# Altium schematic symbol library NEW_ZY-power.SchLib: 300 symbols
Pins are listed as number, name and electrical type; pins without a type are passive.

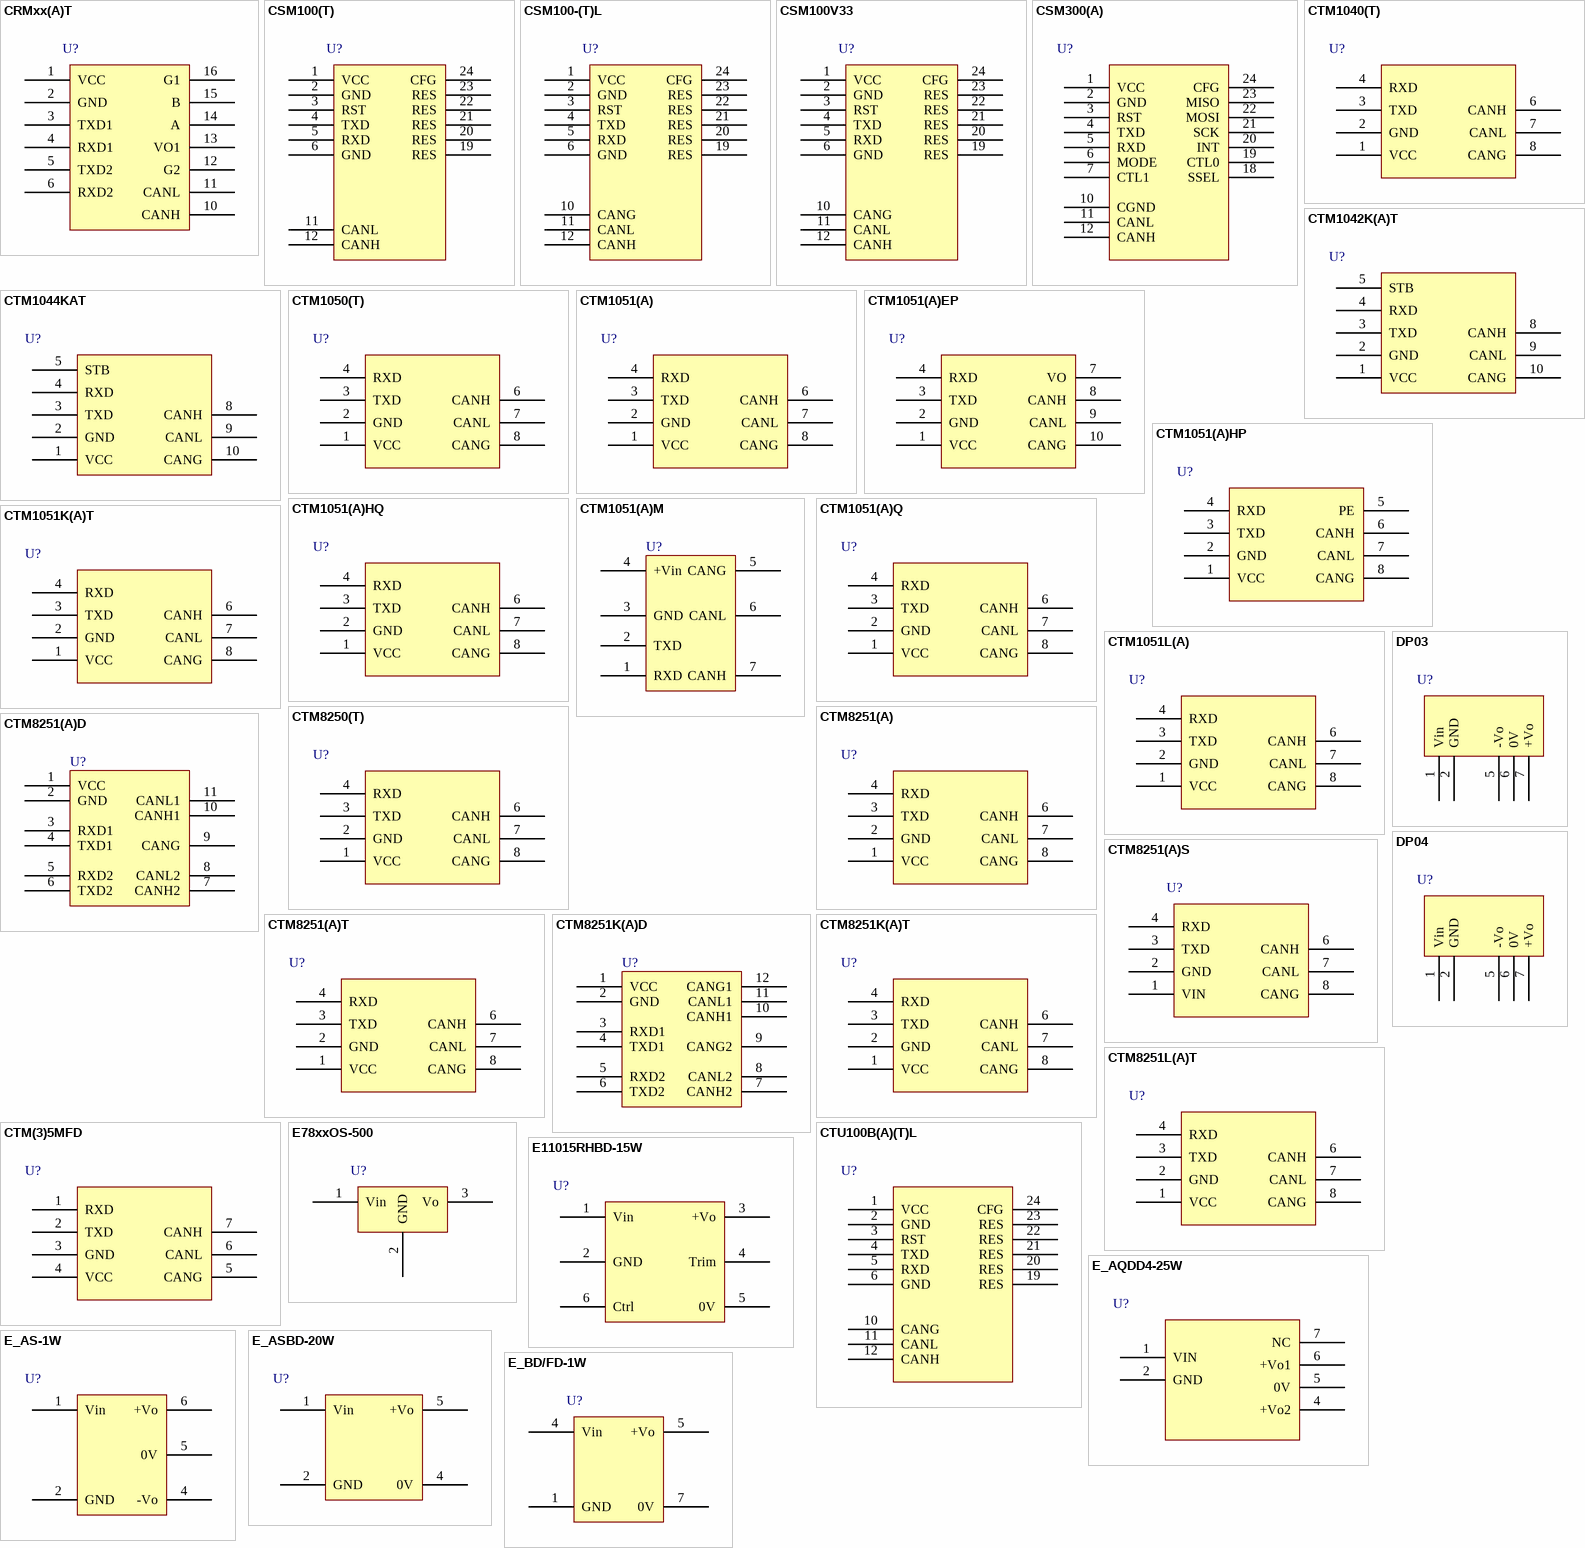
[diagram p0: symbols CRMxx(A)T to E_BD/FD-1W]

## CRMxx(A)T
designator U?
footprint CRMxx(A)T
pins: 1 VCC, 2 GND, 3 TXD1, 4 RXD1, 5 TXD2, 6 RXD2, 10 CANH, 11 CANL, 12 G2, 13 VO1, 14 A, 15 B, 16 G1

## CSM100(T)
designator U?
footprint CSM100(T) (嵌入式CAN-bus接口芯片)
pins: 1 VCC, 2 GND, 3 RST, 4 TXD, 5 RXD, 6 GND, 11 CANL, 12 CANH, 19 RES, 20 RES, 21 RES, 22 RES, 23 RES, 24 CFG

## CSM100-(T)L
designator U?
footprint CSM100-(T)L
pins: 1 VCC, 2 GND, 3 RST, 4 TXD, 5 RXD, 6 GND, 10 CANG, 11 CANL, 12 CANH, 19 RES, 20 RES, 21 RES, 22 RES, 23 RES, 24 CFG

## CSM100V33
designator U?
footprint CSM100V33
pins: 1 VCC, 2 GND, 3 RST, 4 TXD, 5 RXD, 6 GND, 10 CANG, 11 CANL, 12 CANH, 19 RES, 20 RES, 21 RES, 22 RES, 23 RES, 24 CFG

## CSM300(A)
designator U?
footprint CSM300(A)
pins: 1 VCC, 2 GND, 3 RST, 4 TXD, 5 RXD, 6 MODE, 7 CTL1, 10 CGND, 11 CANL, 12 CANH, 18 SSEL, 19 CTL0, 20 INT, 21 SCK, 22 MOSI, 23 MISO, 24 CFG

## CTM1040(T)
designator U?
footprint CTM1040(T)
pins: 1 VCC, 2 GND, 3 TXD, 4 RXD, 6 CANH, 7 CANL, 8 CANG

## CTM1042K(A)T
designator U?
footprint CTM1042K(A)T
pins: 1 VCC, 2 GND, 3 TXD, 4 RXD, 5 STB, 8 CANH, 9 CANL, 10 CANG

## CTM1044KAT
designator U?
footprint CTM1044KAT
pins: 1 VCC, 2 GND, 3 TXD, 4 RXD, 5 STB, 8 CANH, 9 CANL, 10 CANG

## CTM1050(T)
designator U?
footprint CTM1050(T)
pins: 1 VCC, 2 GND, 3 TXD, 4 RXD, 6 CANH, 7 CANL, 8 CANG

## CTM1051(A)
designator U?
footprint CTM1051(A)
pins: 1 VCC, 2 GND, 3 TXD, 4 RXD, 6 CANH, 7 CANL, 8 CANG

## CTM1051(A)EP
designator U?
footprint CTM1051(A)EP (Footprint not found)
pins: 1 VCC, 2 GND, 3 TXD, 4 RXD, 7 VO, 8 CANH, 9 CANL, 10 CANG

## CTM1051(A)HP
designator U?
footprint CTM1051(A)HP
pins: 1 VCC, 2 GND, 3 TXD, 4 RXD, 5 PE, 6 CANH, 7 CANL, 8 CANG

## CTM1051(A)HQ
designator U?
footprint CTM1051(A)HQ
pins: 1 VCC, 2 GND, 3 TXD, 4 RXD, 6 CANH, 7 CANL, 8 CANG

## CTM1051(A)M
designator U?
footprint CTM1051(A)M
pins: 1 RXD, 2 TXD, 3 GND, 4 +Vin, 5 CANG, 6 CANL, 7 CANH

## CTM1051(A)Q
designator U?
footprint CTM1051(A)Q
pins: 1 VCC, 2 GND, 3 TXD, 4 RXD, 6 CANH, 7 CANL, 8 CANG

## CTM1051K(A)T
designator U?
footprint CTM1051K(A)T
pins: 1 VCC, 2 GND, 3 TXD, 4 RXD, 6 CANH, 7 CANL, 8 CANG

## CTM1051L(A)
designator U?
footprint CTM1051L(A)
pins: 1 VCC, 2 GND, 3 TXD, 4 RXD, 6 CANH, 7 CANL, 8 CANG

## CTM8250(T)
designator U?
footprint CTM8250(T)
pins: 1 VCC, 2 GND, 3 TXD, 4 RXD, 6 CANH, 7 CANL, 8 CANG

## CTM8251(A)
designator U?
footprint CTM8251(A)
pins: 1 VCC, 2 GND, 3 TXD, 4 RXD, 6 CANH, 7 CANL, 8 CANG

## CTM8251(A)D
designator U?
footprint CTM8251(A)D
pins: 1 VCC, 2 GND, 3 RXD1, 4 TXD1, 5 RXD2, 6 TXD2, 7 CANH2, 8 CANL2, 9 CANG, 10 CANH1, 11 CANL1

## CTM8251(A)S
designator U?
footprint CTM8251(A)S
pins: 1 VIN, 2 GND, 3 TXD, 4 RXD, 6 CANH, 7 CANL, 8 CANG

## CTM8251(A)T
designator U?
footprint CTM8251(A)T
pins: 1 VCC, 2 GND, 3 TXD, 4 RXD, 6 CANH, 7 CANL, 8 CANG

## CTM8251K(A)D
designator U?
footprint CTM8251K(A)D
pins: 1 VCC, 2 GND, 3 RXD1, 4 TXD1, 5 RXD2, 6 TXD2, 7 CANH2, 8 CANL2, 9 CANG2, 10 CANH1, 11 CANL1, 12 CANG1

## CTM8251K(A)T
designator U?
footprint CTM8251K(A)T
pins: 1 VCC, 2 GND, 3 TXD, 4 RXD, 6 CANH, 7 CANL, 8 CANG

## CTM8251L(A)T
designator U?
footprint CTM8251L(A)T
pins: 1 VCC, 2 GND, 3 TXD, 4 RXD, 6 CANH, 7 CANL, 8 CANG

## CTM(3)5MFD
designator U?
footprint CTM(3)5MFD
pins: 1 RXD, 2 TXD, 3 GND, 4 VCC, 5 CANG, 6 CANL, 7 CANH

## CTU100B(A)(T)L
designator U?
footprint CTU100B(A)(T)L
pins: 1 VCC, 2 GND, 3 RST, 4 TXD, 5 RXD, 6 GND, 10 CANG, 11 CANL, 12 CANH, 19 RES, 20 RES, 21 RES, 22 RES, 23 RES, 24 CFG

## DP03
designator U?
footprint DP03
pins: 1 Vin, 2 GND, 5 -Vo, 6 0V, 7 +Vo

## DP04
designator U?
footprint DP04
pins: 1 Vin, 2 GND, 5 -Vo, 6 0V, 7 +Vo

## E78xxOS-500
designator U?
footprint E78xxOS-500
pins: 1 Vin, 2 GND, 3 Vo

## E11015RHBD-15W
designator U?
footprint E11015RHBD-15W
pins: 1 Vin, 2 GND, 3 +Vo, 4 Trim, 5 0V, 6 Ctrl

## E_AQDD4-25W
designator U?
footprint E_AQDD4-25W
pins: 1 VIN, 2 GND, 4 +Vo2, 5 0V, 6 +Vo1, 7 NC

## E_AS-1W
designator U?
footprint E_AS-1W
pins: 1 Vin, 2 GND, 4 -Vo, 5 0V, 6 +Vo

## E_ASBD-20W
designator U?
footprint E_ASBD-20W
pins: 1 Vin, 2 GND, 4 0V, 5 +Vo

## E_BD/FD-1W
designator U?
footprint E_BD/FD-1W
pins: 1 GND, 4 Vin, 5 +Vo, 7 0V

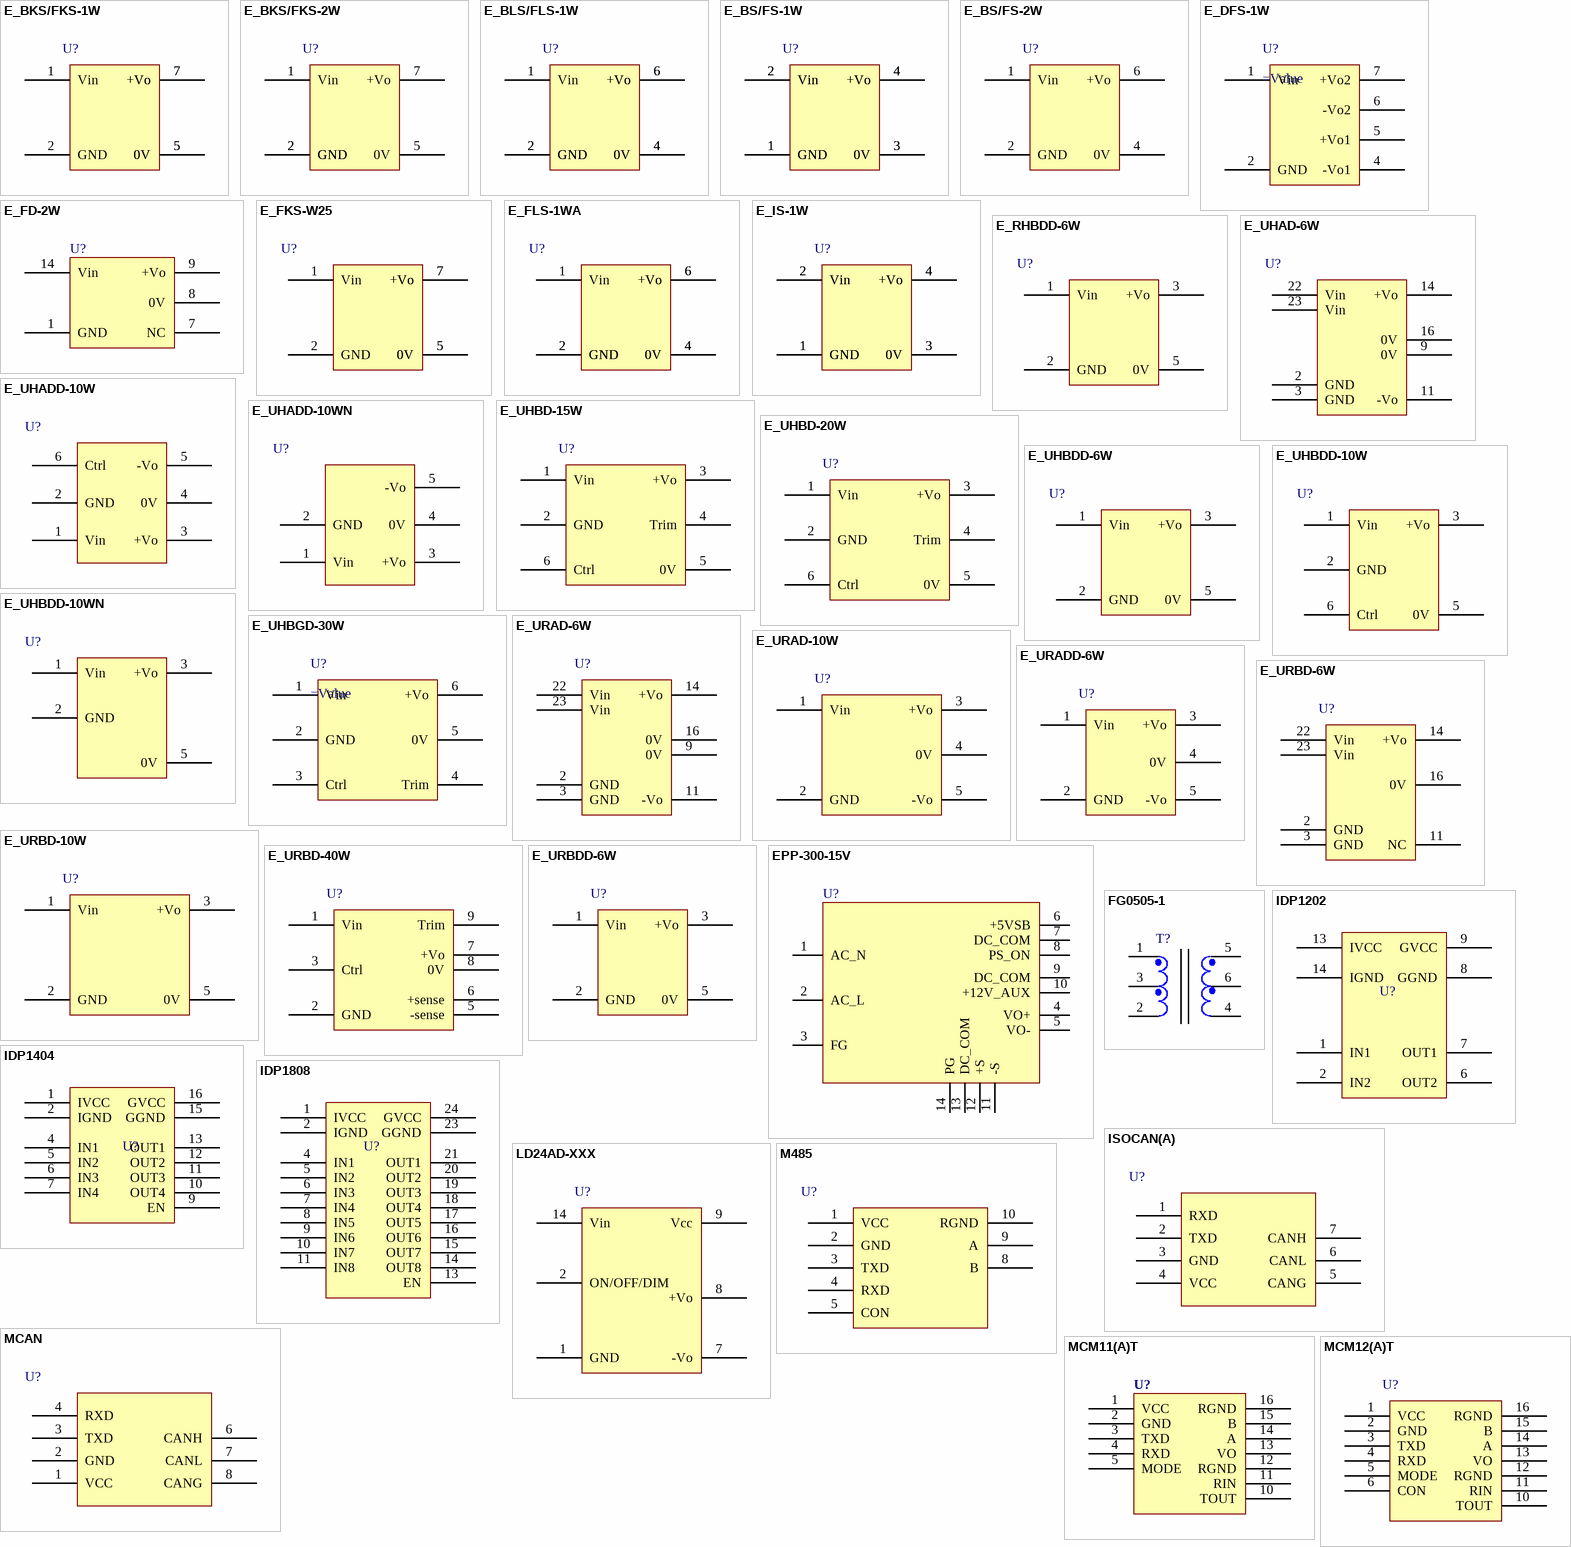
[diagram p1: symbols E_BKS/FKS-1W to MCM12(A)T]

## E_BKS/FKS-1W
designator U?
footprint E_BKS/FKS-1W
pins: 1 Vin, 2 GND, 5 0V, 5 0V, 7 +Vo, 7 +Vo

## E_BKS/FKS-2W
designator U?
footprint E_BKS/FKS-2W
pins: 1 Vin, 2 GND, 2 GND, 5 0V, 7 +Vo

## E_BLS/FLS-1W
designator U?
footprint E_BLS/FLS-1W
pins: 1 Vin, 2 GND, 2 GND, 4 0V, 4 0V, 6 +Vo, 6 +Vo

## E_BS/FS-1W
designator U?
footprint E_BS/FS-1W
pins: 1 GND, 1 GND, 2 Vin, 2 Vin, 3 0V, 3 0V, 4 +Vo, 4 +Vo

## E_BS/FS-2W
designator U?
footprint E_BS/FS-2W
pins: 1 Vin, 2 GND, 4 0V, 6 +Vo

## E_DFS-1W
designator U?
footprint E_DFS-1W
pins: 1 Vin, 2 GND, 4 -Vo1, 5 +Vo1, 6 -Vo2, 7 +Vo2

## E_FD-2W
designator U?
footprint E_FD-2W
pins: 1 GND, 7 NC, 8 0V, 9 +Vo, 14 Vin

## E_FKS-W25
designator U?
footprint E_FKS-W25
pins: 1 Vin, 2 GND, 5 0V, 5 0V, 7 +Vo, 7 +Vo

## E_FLS-1WA
designator U?
footprint E_FLS-1WA
pins: 1 Vin, 2 GND, 2 GND, 4 0V, 4 0V, 6 +Vo, 6 +Vo

## E_IS-1W
designator U?
footprint E_IS-1W
pins: 1 GND, 1 GND, 2 Vin, 2 Vin, 3 0V, 3 0V, 4 +Vo, 4 +Vo

## E_RHBDD-6W
designator U?
footprint E_RHBDD-6W
pins: 1 Vin, 2 GND, 3 +Vo, 5 0V

## E_UHAD-6W
designator U?
footprint E_UHAD-6W
pins: 2 GND, 3 GND, 9 0V, 11 -Vo, 14 +Vo, 16 0V, 22 Vin, 23 Vin

## E_UHADD-10W
designator U?
footprint E_UHADD-10W
pins: 1 Vin, 2 GND, 3 +Vo, 4 0V, 5 -Vo, 6 Ctrl

## E_UHADD-10WN
designator U?
footprint E_UHADD-10WN
pins: 1 Vin, 2 GND, 3 +Vo, 4 0V, 5 -Vo

## E_UHBD-15W
designator U?
footprint E_UHBD-15W
pins: 1 Vin, 2 GND, 3 +Vo, 4 Trim, 5 0V, 6 Ctrl

## E_UHBD-20W
designator U?
footprint E_UHBD-20W
pins: 1 Vin, 2 GND, 3 +Vo, 4 Trim, 5 0V, 6 Ctrl

## E_UHBDD-6W
designator U?
footprint E_UHBDD-6W
pins: 1 Vin, 2 GND, 3 +Vo, 5 0V

## E_UHBDD-10W
designator U?
footprint E_UHBDD-10W
pins: 1 Vin, 2 GND, 3 +Vo, 5 0V, 6 Ctrl

## E_UHBDD-10WN
designator U?
footprint E_UHBDD-10WN
pins: 1 Vin, 2 GND, 3 +Vo, 5 0V

## E_UHBGD-30W
designator U?
footprint E_UHBGD-30W
pins: 1 Vin, 2 GND, 3 Ctrl, 4 Trim, 5 0V, 6 +Vo

## E_URAD-6W
designator U?
footprint E_URAD-6W
pins: 2 GND, 3 GND, 9 0V, 11 -Vo, 14 +Vo, 16 0V, 22 Vin, 23 Vin

## E_URAD-10W
designator U?
footprint E_URAD-10W
pins: 1 Vin, 2 GND, 3 +Vo, 4 0V, 5 -Vo

## E_URADD-6W
designator U?
footprint E_URADD-6W
pins: 1 Vin, 2 GND, 3 +Vo, 4 0V, 5 -Vo

## E_URBD-6W
designator U?
footprint E_URBD-6W
pins: 2 GND, 3 GND, 11 NC, 14 +Vo, 16 0V, 22 Vin, 23 Vin

## E_URBD-10W
designator U?
footprint E_URBD-10W
pins: 1 Vin, 2 GND, 3 +Vo, 5 0V

## E_URBD-40W
designator U?
footprint E_URBD-40W
pins: 1 Vin, 2 GND, 3 Ctrl, 5 -sense, 6 +sense, 7 +Vo, 8 0V, 9 Trim

## E_URBDD-6W
designator U?
footprint E_URBDD-6W
pins: 1 Vin, 2 GND, 3 +Vo, 5 0V

## EPP-300-15V
designator U?
footprint epp-300-15V
pins: 1 AC_N, 2 AC_L, 3 FG, 4 VO+, 5 VO-, 6 +5VSB, 7 DC_COM, 8 PS_ON, 9 DC_COM, 10 +12V_AUX, 11 -S, 12 +S, 13 DC_COM, 14 PG

## FG0505-1
designator T?
TRANS6D
footprint FG0505-1
pins: 1, 2, 3, 4, 5, 6

## IDP1202
designator U?
footprint IDP1202 (20x10x8mm)
pins: 1 IN1, 2 IN2, 6 OUT2, 7 OUT1, 8 GGND, 9 GVCC, 13 IVCC, 14 IGND

## IDP1404
designator U?
footprint IDP1404 (23.97x14.41x9.65mm)
pins: 1 IVCC, 2 IGND, 4 IN1, 5 IN2, 6 IN3, 7 IN4, 9 EN, 10 OUT4, 11 OUT3, 12 OUT2, 13 OUT1, 15 GGND, 16 GVCC

## IDP1808
designator U?
footprint IDP1808 (32.32x14.41x6.7(9.65)mm)
pins: 1 IVCC, 2 IGND, 4 IN1, 5 IN2, 6 IN3, 7 IN4, 8 IN5, 9 IN6, 10 IN7, 11 IN8, 13 EN, 14 OUT8, 15 OUT7, 16 OUT6, 17 OUT5, 18 OUT4, 19 OUT3, 20 OUT2, 21 OUT1, 23 GGND, 24 GVCC

## ISOCAN(A)
designator U?
footprint ISOCAN(A)
pins: 1 RXD, 2 TXD, 3 GND, 4 VCC, 5 CANG, 6 CANL, 7 CANH

## LD24AD-XXX
designator U?
footprint LD24AD-XXX
pins: 1 GND, 2 ON/OFF/DIM, 7 -Vo, 8 +Vo, 9 Vcc, 14 Vin

## M485
designator U?
footprint M485
pins: 1 VCC, 2 GND, 3 TXD, 4 RXD, 5 CON, 8 B, 9 A, 10 RGND

## MCAN
designator U?
footprint MCAN
pins: 1 VCC, 2 GND, 3 TXD, 4 RXD, 6 CANH, 7 CANL, 8 CANG

## MCM11(A)T
designator U?
footprint MCM11(A)T
pins: 1 VCC, 2 GND, 3 TXD, 4 RXD, 5 MODE, 10 TOUT, 11 RIN, 12 RGND, 13 VO, 14 A, 15 B, 16 RGND

## MCM12(A)T
designator U?
footprint MCM12(A)T
pins: 1 VCC, 2 GND, 3 TXD, 4 RXD, 5 MODE, 6 CON, 10 TOUT, 11 RIN, 12 RGND, 13 VO, 14 A, 15 B, 16 RGND

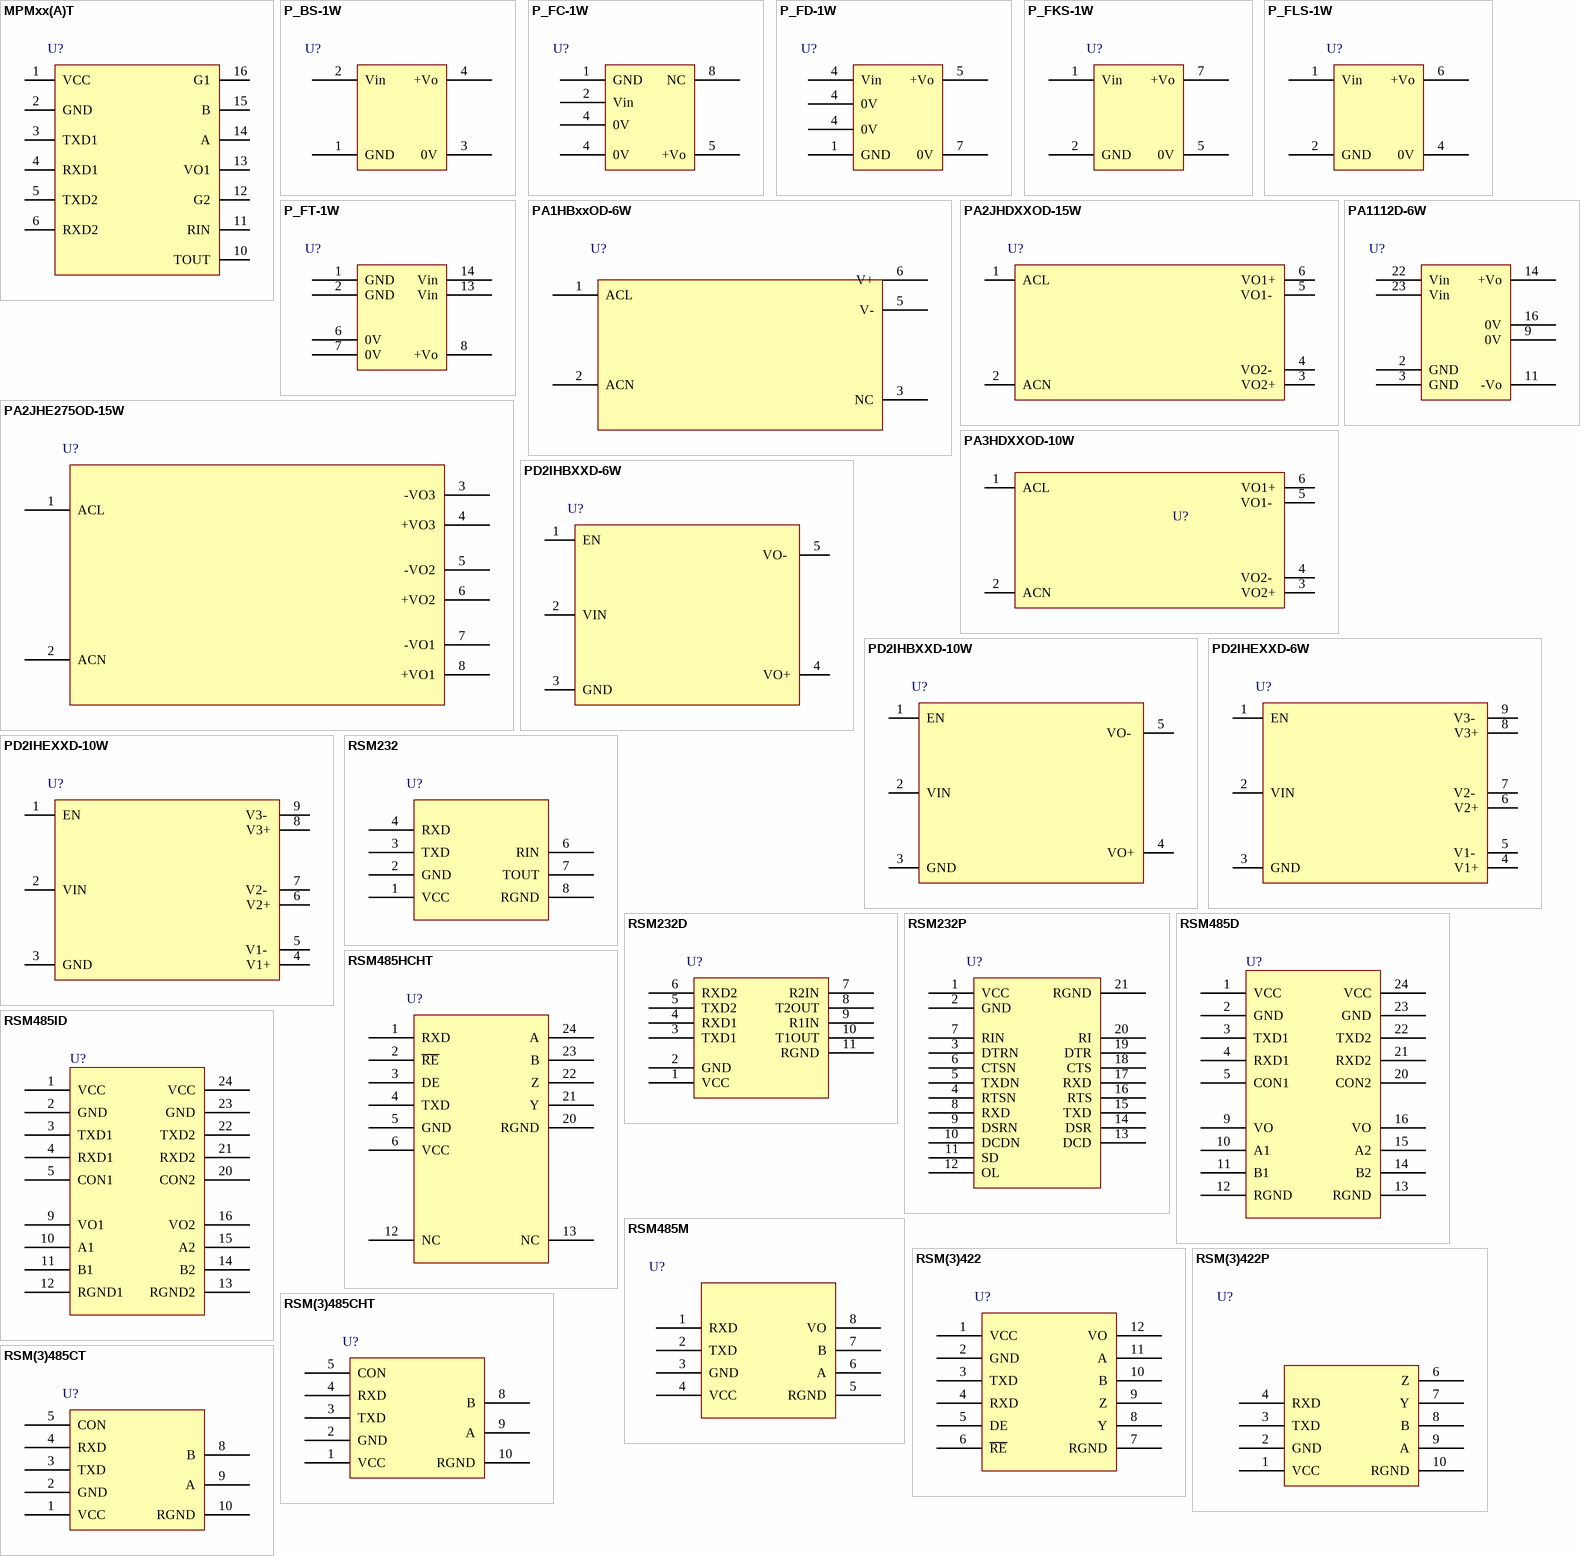
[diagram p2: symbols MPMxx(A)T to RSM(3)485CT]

## MPMxx(A)T
designator U?
footprint MPMxx(A)T
pins: 1 VCC, 2 GND, 3 TXD1, 4 RXD1, 5 TXD2, 6 RXD2, 10 TOUT, 11 RIN, 12 G2, 13 VO1, 14 A, 15 B, 16 G1

## P_BS-1W
designator U?
footprint Model Name (Footprint not found)
footprint P_BS-1W
pins: 1 GND, 2 Vin, 3 0V, 4 +Vo

## P_FC-1W
designator U?
footprint P_FC-1W
pins: 1 GND, 2 Vin, 4 0V, 4 0V, 5 +Vo, 8 NC

## P_FD-1W
designator U?
footprint P_FD-1W
pins: 1 GND, 4 Vin, 4 0V, 4 0V, 5 +Vo, 7 0V

## P_FKS-1W
designator U?
footprint P_FKS-1W
pins: 1 Vin, 2 GND, 5 0V, 7 +Vo

## P_FLS-1W
designator U?
footprint P_FLS-1W
pins: 1 Vin, 2 GND, 4 0V, 6 +Vo

## P_FT-1W
designator U?
footprint P_FT-1W
pins: 1 GND, 2 GND, 6 0V, 7 0V, 8 +Vo, 13 Vin, 14 Vin

## PA1HBxxOD-6W
designator U?
footprint PA1HBxxOD-6W
pins: 1 ACL, 2 ACN, 3 NC, 5 V-, 6 V+

## PA2JHDXXOD-15W
designator U?
footprint PA2JHDXXOD-15W
pins: 1 ACL, 2 ACN, 3 VO2+, 4 VO2- , 5 VO1- , 6 VO1+

## PA2JHE275OD-15W
designator U?
footprint PA2JHE275OD-15W
pins: 1 ACL, 2 ACN, 3 -VO3, 4 +VO3, 5 -VO2, 6 +VO2, 7 -VO1, 8 +VO1

## PA3HDXXOD-10W
designator U?
footprint PA3HDXXOD-10W
pins: 1 ACL, 2 ACN, 3 VO2+, 4 VO2- , 5 VO1- , 6 VO1+

## PA1112D-6W
designator U?
footprint PA1112D-6W
pins: 2 GND, 3 GND, 9 0V, 11 -Vo, 14 +Vo, 16 0V, 22 Vin, 23 Vin

## PD2IHBXXD-6W
designator U?
footprint PD2IHBXXD-6W
pins: 1 EN, 2 VIN, 3 GND, 4 VO+, 5 VO- 

## PD2IHBXXD-10W
designator U?
footprint PD2IHBXXD-10W
pins: 1 EN, 2 VIN, 3 GND, 4 VO+, 5 VO- 

## PD2IHEXXD-6W
designator U?
footprint PD2IHEXXD-6W
pins: 1 EN, 2 VIN, 3 GND, 4 V1+, 5 V1- , 6 V2+, 7 V2- , 8 V3+, 9 V3- 

## PD2IHEXXD-10W
designator U?
footprint PD2IHEXXD-10W
pins: 1 EN, 2 VIN, 3 GND, 4 V1+, 5 V1- , 6 V2+, 7 V2- , 8 V3+, 9 V3- 

## RSM232
designator U?
footprint RSM232
pins: 1 VCC, 2 GND, 3 TXD, 4 RXD, 6 RIN, 7 TOUT, 8 RGND

## RSM232D
designator U?
footprint RSM232D
pins: 1 VCC, 2 GND, 3 TXD1, 4 RXD1, 5 TXD2, 6 RXD2, 7 R2IN, 8 T2OUT, 9 R1IN, 10 T1OUT, 11 RGND

## RSM232P
designator U?
footprint RSM232P
pins: 1 VCC, 2 GND, 3 DTRN, 4 RTSN, 5 TXDN, 6 CTSN, 7 RIN, 8 RXD, 9 DSRN, 10 DCDN, 11 SD, 12 OL, 13 DCD, 14 DSR, 15 TXD, 16 RTS, 17 RXD, 18 CTS, 19 DTR, 20 RI, 21 RGND

## RSM485D
designator U?
footprint RSM485D
pins: 1 VCC, 2 GND, 3 TXD1, 4 RXD1, 5 CON1, 9 VO, 10 A1, 11 B1, 12 RGND, 13 RGND, 14 B2, 15 A2, 16 VO, 20 CON2, 21 RXD2, 22 TXD2, 23 GND, 24 VCC
2 alternate drawings of the same symbol

## RSM485HCHT
designator U?
footprint RSM485HCHT
pins: 1 RXD, 2 ~{RE}, 3 DE, 4 TXD, 5 GND, 6 VCC, 12 NC, 13 NC, 20 RGND, 21 Y, 22 Z, 23 B, 24 A

## RSM485ID
designator U?
footprint RSM485ID
pins: 1 VCC, 2 GND, 3 TXD1, 4 RXD1, 5 CON1, 9 VO1, 10 A1, 11 B1, 12 RGND1, 13 RGND2, 14 B2, 15 A2, 16 VO2, 20 CON2, 21 RXD2, 22 TXD2, 23 GND, 24 VCC
2 alternate drawings of the same symbol

## RSM485M
designator U?
footprint RSM485M
pins: 1 RXD, 2 TXD, 3 GND, 4 VCC, 5 RGND, 6 A, 7 B, 8 VO

## RSM(3)422
designator U?
footprint RSM(3)422
pins: 1 VCC, 2 GND, 3 TXD, 4 RXD, 5 DE, 6 ~{RE}, 7 RGND, 8 Y, 9 Z, 10 B, 11 A, 12 VO

## RSM(3)422P
designator U?
footprint RSM(3)422P
pins: 1 VCC, 2 GND, 3 TXD, 4 RXD, 6 Z, 7 Y, 8 B, 9 A, 10 RGND
2 alternate drawings of the same symbol

## RSM(3)485CHT
designator U?
footprint RSM(3)485CHT (嵌入式隔离RS-485收发器)
pins: 1 VCC, 2 GND, 3 TXD, 4 RXD, 5 CON, 8 B, 9 A, 10 RGND

## RSM(3)485CT
designator U?
footprint RSM(3)485CT (嵌入式隔离RS-485收发器)
pins: 1 VCC, 2 GND, 3 TXD, 4 RXD, 5 CON, 8 B, 9 A, 10 RGND

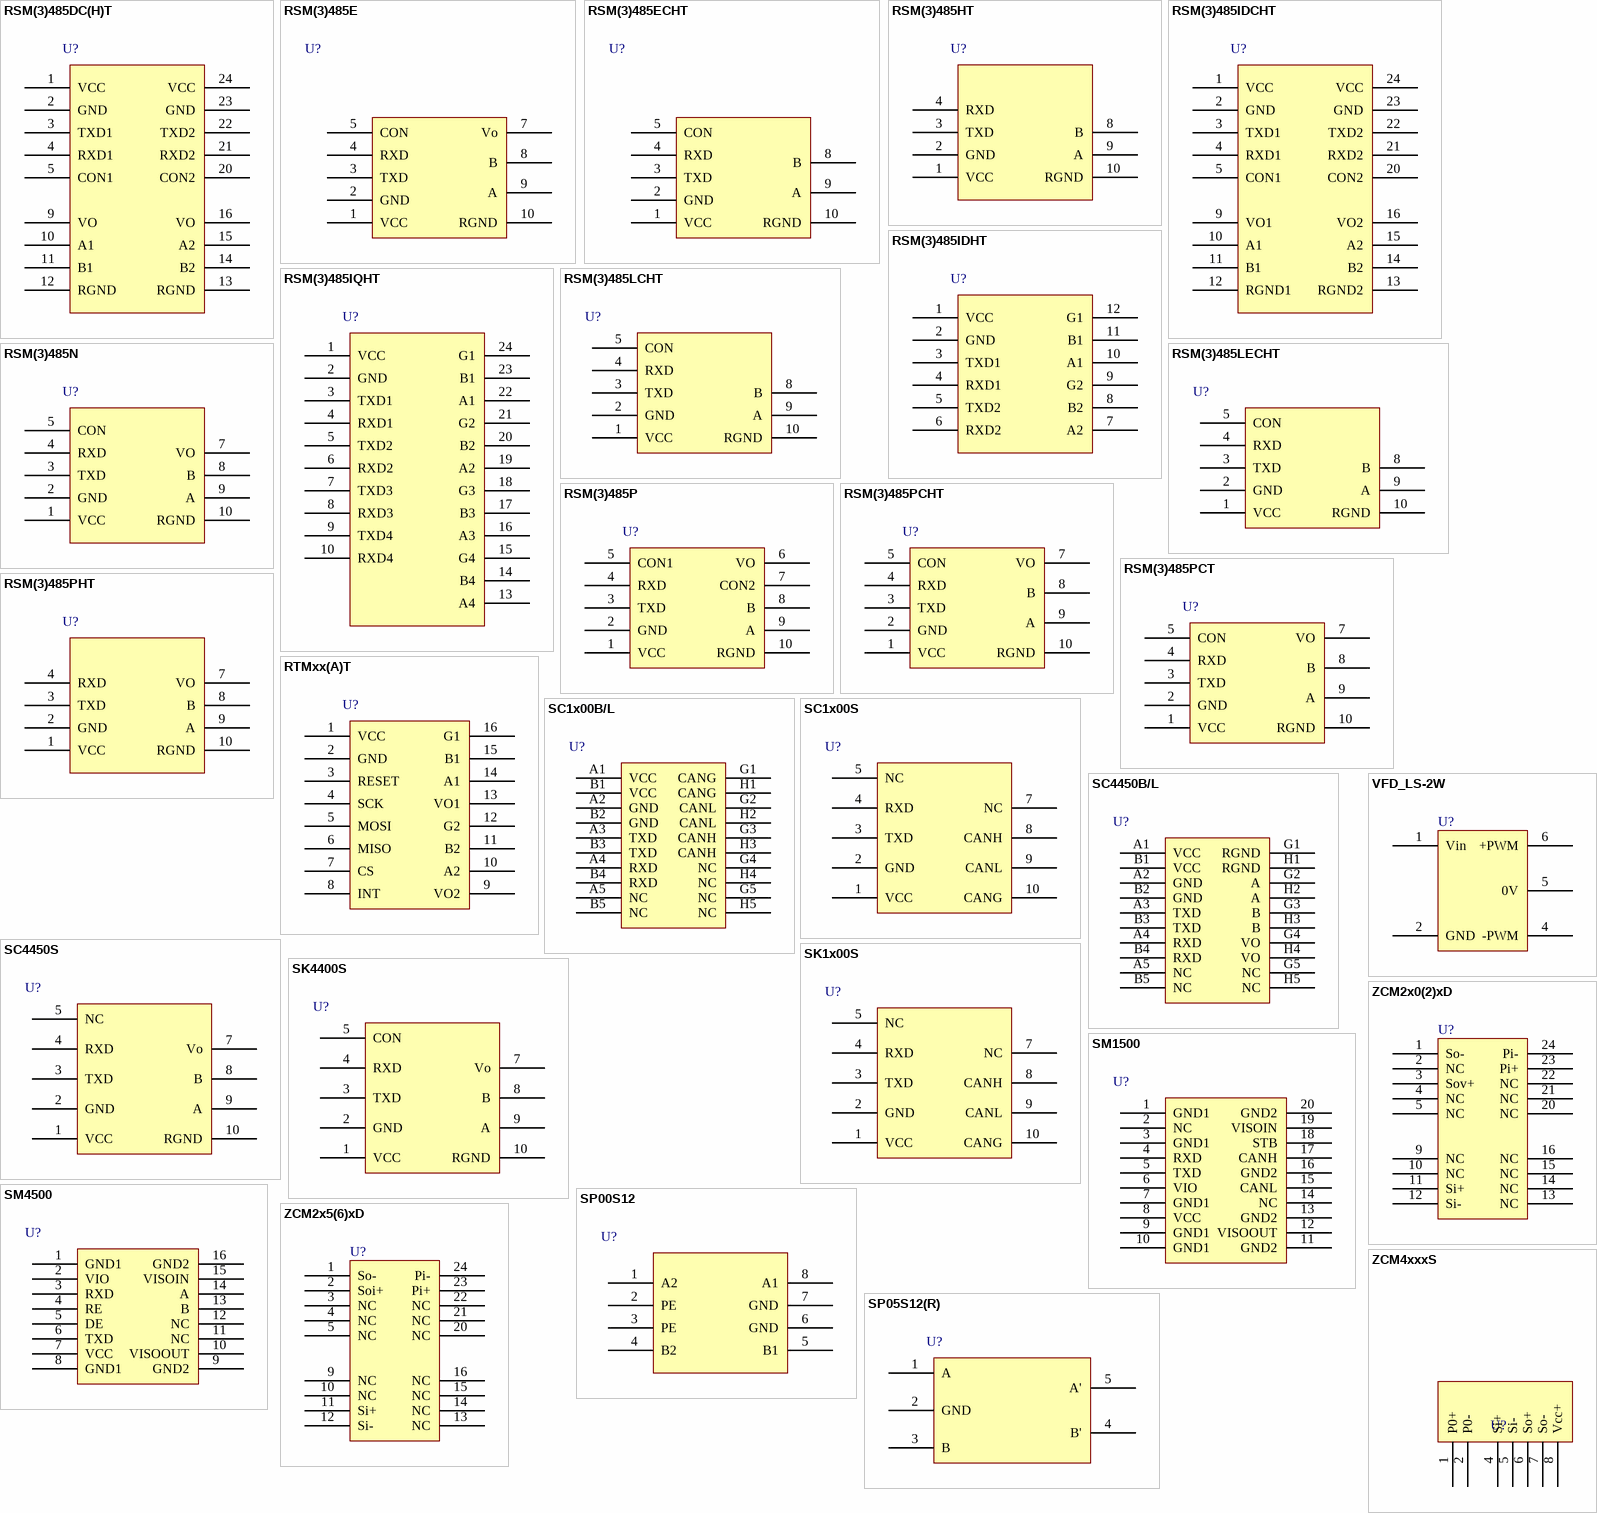
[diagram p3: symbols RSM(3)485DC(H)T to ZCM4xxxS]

## RSM(3)485DC(H)T
designator U?
footprint RSM(3)485DC(H)T
pins: 1 VCC, 2 GND, 3 TXD1, 4 RXD1, 5 CON1, 9 VO, 10 A1, 11 B1, 12 RGND, 13 RGND, 14 B2, 15 A2, 16 VO, 20 CON2, 21 RXD2, 22 TXD2, 23 GND, 24 VCC

## RSM(3)485E
designator U?
footprint RSM(3)485E
pins: 1 VCC, 2 GND, 3 TXD, 4 RXD, 5 CON, 7 Vo, 8 B, 9 A, 10 RGND
2 alternate drawings of the same symbol

## RSM(3)485ECHT
designator U?
footprint RSM(3)485ECHT
pins: 1 VCC, 2 GND, 3 TXD, 4 RXD, 5 CON, 8 B, 9 A, 10 RGND
2 alternate drawings of the same symbol

## RSM(3)485HT
designator U?
footprint RSM(3)485HT
pins: 1 VCC, 2 GND, 3 TXD, 4 RXD, 8 B, 9 A, 10 RGND

## RSM(3)485IDCHT
designator U?
footprint RSM(3)485IDCHT
pins: 1 VCC, 2 GND, 3 TXD1, 4 RXD1, 5 CON1, 9 VO1, 10 A1, 11 B1, 12 RGND1, 13 RGND2, 14 B2, 15 A2, 16 VO2, 20 CON2, 21 RXD2, 22 TXD2, 23 GND, 24 VCC

## RSM(3)485IDHT
designator U?
footprint RSM(3)485IDHT
pins: 1 VCC, 2 GND, 3 TXD1, 4 RXD1, 5 TXD2, 6 RXD2, 7 A2, 8 B2, 9 G2, 10 A1, 11 B1, 12 G1

## RSM(3)485IQHT
designator U?
footprint RSM(3)485IQHT
pins: 1 VCC, 2 GND, 3 TXD1, 4 RXD1, 5 TXD2, 6 RXD2, 7 TXD3, 8 RXD3, 9 TXD4, 10 RXD4, 13 A4, 14 B4, 15 G4, 16 A3, 17 B3, 18 G3, 19 A2, 20 B2, 21 G2, 22 A1, 23 B1, 24 G1

## RSM(3)485LCHT
designator U?
footprint RSM(3)485LCHT
pins: 1 VCC, 2 GND, 3 TXD, 4 RXD, 5 CON, 8 B, 9 A, 10 RGND

## RSM(3)485LECHT
designator U?
footprint RSM(3)485LECHT
pins: 1 VCC, 2 GND, 3 TXD, 4 RXD, 5 CON, 8 B, 9 A, 10 RGND

## RSM(3)485N
designator U?
footprint RSM(3)485N
pins: 1 VCC, 2 GND, 3 TXD, 4 RXD, 5 CON, 7 VO, 8 B, 9 A, 10 RGND

## RSM(3)485P
designator U?
footprint RSM(3)485P
pins: 1 VCC, 2 GND, 3 TXD, 4 RXD, 5 CON1, 6 VO, 7 CON2, 8 B, 9 A, 10 RGND

## RSM(3)485PCHT
designator U?
footprint RSM(3)485PCHT
pins: 1 VCC, 2 GND, 3 TXD, 4 RXD, 5 CON, 7 VO, 8 B, 9 A, 10 RGND

## RSM(3)485PCT
designator U?
footprint RSM(3)485PCT
pins: 1 VCC, 2 GND, 3 TXD, 4 RXD, 5 CON, 7 VO, 8 B, 9 A, 10 RGND

## RSM(3)485PHT
designator U?
footprint RSM(3)485PHT
pins: 1 VCC, 2 GND, 3 TXD, 4 RXD, 7 VO, 8 B, 9 A, 10 RGND

## RTMxx(A)T
designator U?
footprint RTMxx(A)T
pins: 1 VCC, 2 GND, 3 RESET, 4 SCK, 5 MOSI, 6 MISO, 7 CS, 8 INT, 9 VO2, 10 A2, 11 B2, 12 G2, 13 VO1, 14 A1, 15 B1, 16 G1

## SC1x00B/L
designator U?
footprint SC1x00B/L
pins: A1 VCC, A2 GND, A3 TXD, A4 RXD, A5 NC, B1 VCC, B2 GND, B3 TXD, B4 RXD, B5 NC, G1 CANG, G2 CANL, G3 CANH, G4 NC, G5 NC, H1 CANG, H2 CANL, H3 CANH, H4 NC, H5 NC

## SC1x00S
designator U?
footprint SC1x00S
pins: 1 VCC, 2 GND, 3 TXD, 4 RXD, 5 NC, 7 NC, 8 CANH, 9 CANL, 10 CANG

## SC4450B/L
designator U?
footprint SC4450B/L
pins: A1 VCC, A2 GND, A3 TXD, A4 RXD, A5 NC, B1 VCC, B2 GND, B3 TXD, B4 RXD, B5 NC, G1 RGND, G2 A, G3 B, G4 VO, G5 NC, H1 RGND, H2 A, H3 B, H4 VO, H5 NC

## SC4450S
designator U?
footprint SC4450S
pins: 1 VCC, 2 GND, 3 TXD, 4 RXD, 5 NC, 7 Vo, 8 B, 9 A, 10 RGND

## SK1x00S
designator U?
footprint SK1x00S
pins: 1 VCC, 2 GND, 3 TXD, 4 RXD, 5 NC, 7 NC, 8 CANH, 9 CANL, 10 CANG

## SK4400S
designator U?
footprint SK4400S
pins: 1 VCC, 2 GND, 3 TXD, 4 RXD, 5 CON, 7 Vo, 8 B, 9 A, 10 RGND

## SM1500
designator U?
footprint SM1500
pins: 1 GND1, 2 NC, 3 GND1, 4 RXD, 5 TXD, 6 VIO, 7 GND1, 8 VCC, 9 GND1, 10 GND1, 11 GND2, 12 VISOOUT, 13 GND2, 14 NC, 15 CANL, 16 GND2, 17 CANH, 18 STB, 19 VISOIN, 20 GND2

## SM4500
designator U?
footprint SM4500
pins: 1 GND1, 2 VIO, 3 RXD, 4 RE, 5 DE, 6 TXD, 7 VCC, 8 GND1, 9 GND2, 10 VISOOUT, 11 NC, 12 NC, 13 B, 14 A, 15 VISOIN, 16 GND2

## SP00S12
designator U?
footprint SP00S12
pins: 1 A2, 2 PE, 3 PE, 4 B2, 5 B1, 6 GND, 7 GND, 8 A1

## SP05S12(R)
designator U?
footprint SP05S12(R)
pins: 1 A, 2 GND, 3 B, 4 B', 5 A'

## VFD_LS-2W
designator U?
footprint VFD_LS-2W
pins: 1 Vin, 2 GND, 4 -PWM, 5 0V, 6 +PWM

## ZCM2x0(2)xD
designator U?
footprint ZCM2x0(2)xD
pins: 1 So-, 2 NC, 3 Sov+, 4 NC, 5 NC, 9 NC, 10 NC, 11 Si+, 12 Si-, 13 NC, 14 NC, 15 NC, 16 NC, 20 NC, 21 NC, 22 NC, 23 Pi+, 24 Pi-

## ZCM2x5(6)xD
designator U?
footprint ZCM2x5(6)xD
pins: 1 So-, 2 Soi+, 3 NC, 4 NC, 5 NC, 9 NC, 10 NC, 11 Si+, 12 Si-, 13 NC, 14 NC, 15 NC, 16 NC, 20 NC, 21 NC, 22 NC, 23 Pi+, 24 Pi-

## ZCM4xxxS
designator U?
footprint ZCM4XXXS
pins: 1 P0+, 2 P0-, 4 Si+, 5 Si-, 6 So+, 7 So-, 8 Vcc+

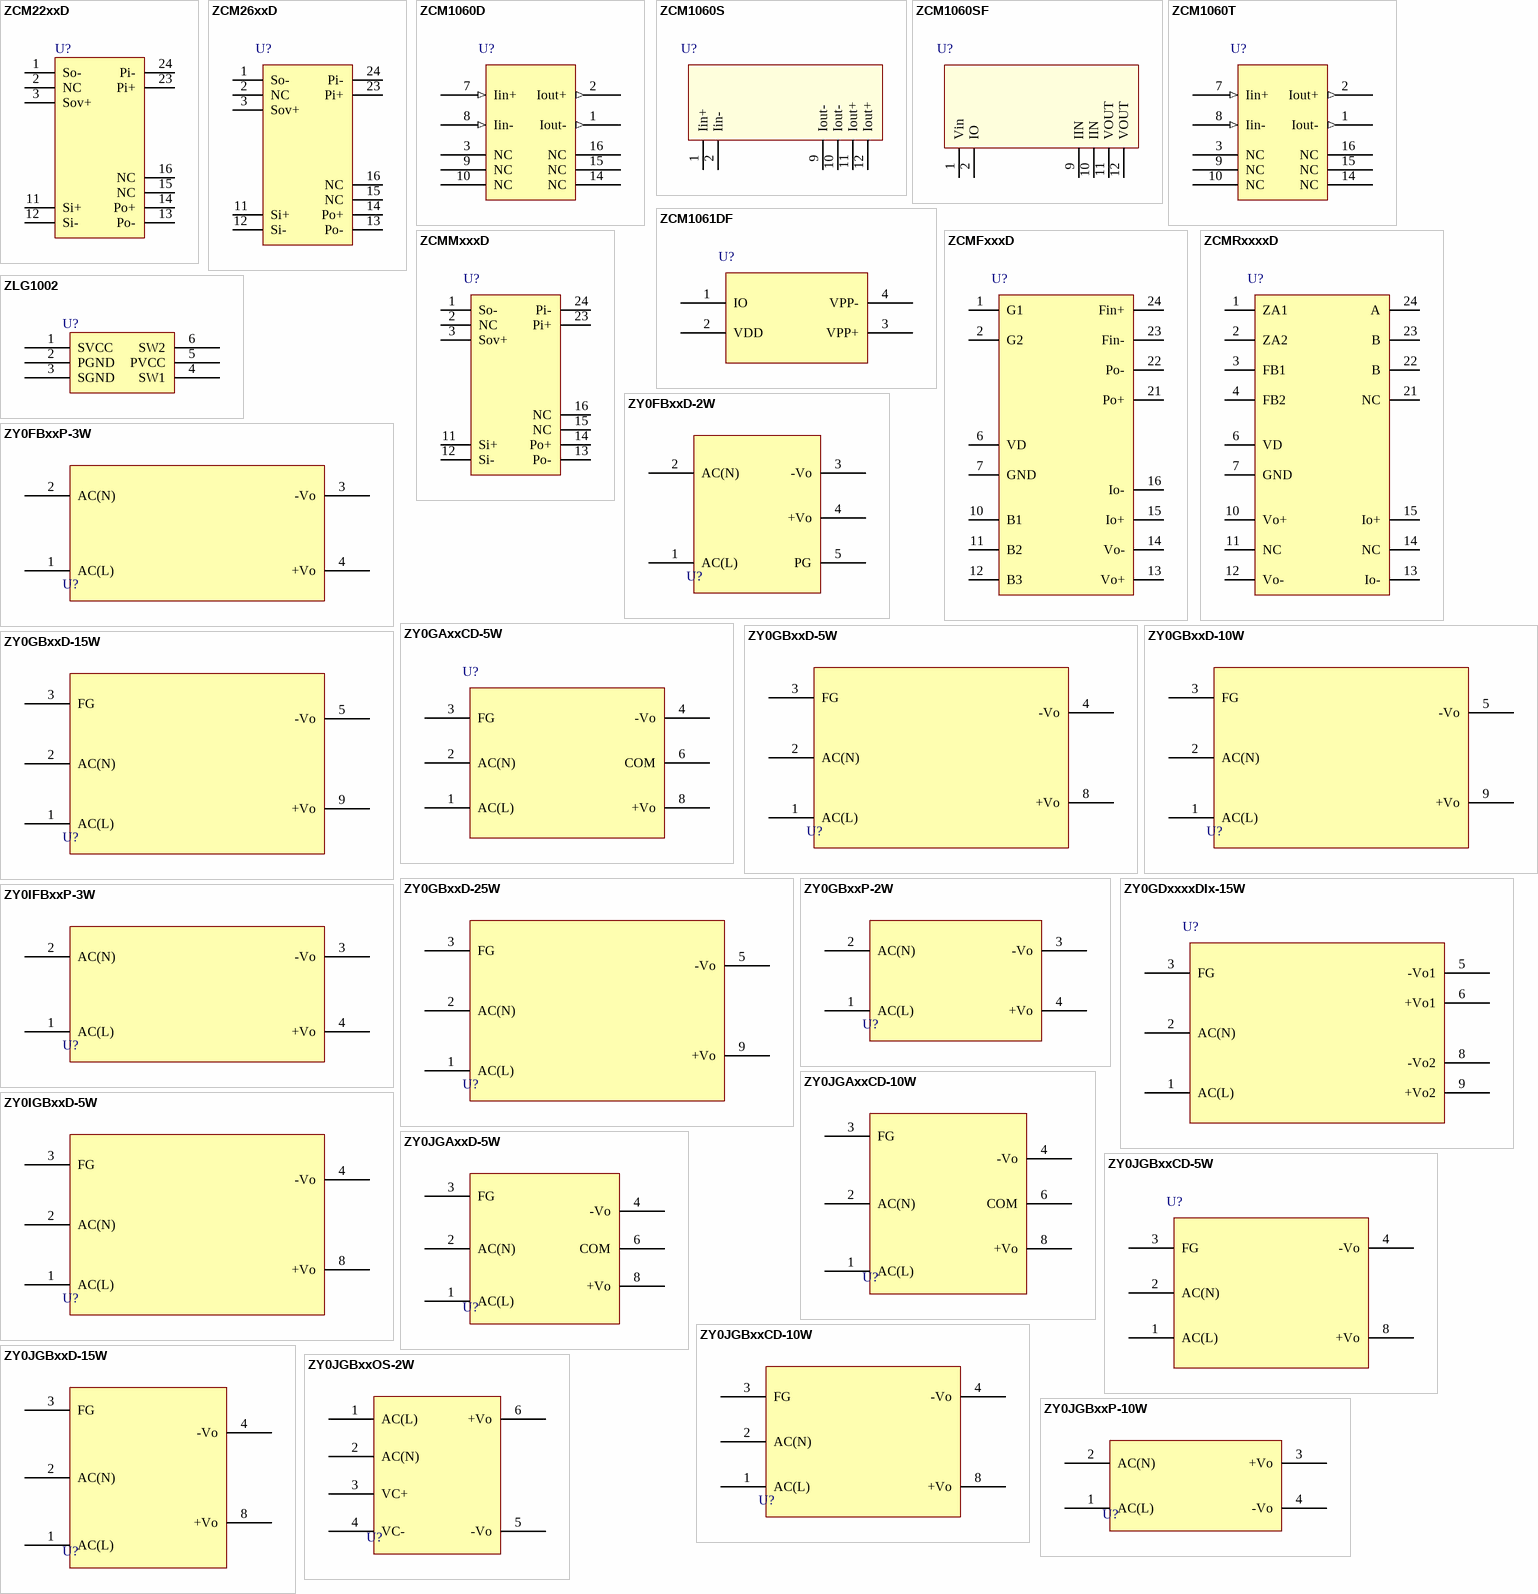
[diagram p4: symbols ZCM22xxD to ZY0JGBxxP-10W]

## ZCM22xxD
designator U?
footprint ZCM22xxD
pins: 1 So-, 2 NC, 3 Sov+, 11 Si+, 12 Si-, 13 Po-, 14 Po+, 15 NC, 16 NC, 23 Pi+, 24 Pi-

## ZCM26xxD
designator U?
footprint ZCM26xxD
pins: 1 So-, 2 NC, 3 Sov+, 11 Si+, 12 Si-, 13 Po-, 14 Po+, 15 NC, 16 NC, 23 Pi+, 24 Pi-

## ZCM1060D
designator U?
footprint ZCM1060D
pins: 1 Iout- (out), 2 Iout+ (out), 3 NC, 7 Iin+ (in), 8 Iin- (in), 9 NC, 10 NC, 14 NC, 15 NC, 16 NC

## ZCM1060S
designator U?
footprint ZCM1060S
pins: 1 Iin+, 2 Iin-, 9 Iout-, 10 Iout-, 11 Iout+, 12 Iout+

## ZCM1060SF
designator U?
footprint ZCM1060SF
pins: 1 Vin, 2 IO, 9 IIN, 10 IIN, 11 VOUT, 12 VOUT

## ZCM1060T
designator U?
footprint ZCM1060T
pins: 1 Iout- (out), 2 Iout+ (out), 3 NC, 7 Iin+ (in), 8 Iin- (in), 9 NC, 10 NC, 14 NC, 15 NC, 16 NC

## ZCM1061DF
designator U?
footprint ZCM1061DF
pins: 1 IO, 2 VDD, 3 VPP+, 4 VPP-

## ZCMFxxxD
designator U?
footprint ZCMFxxxD
pins: 1 G1, 2 G2, 6 VD, 7 GND, 10 B1, 11 B2, 12 B3, 13 Vo+, 14 Vo-, 15 Io+, 16 Io-, 21 Po+, 22 Po-, 23 Fin-, 24 Fin+

## ZCMMxxxD
designator U?
footprint ZCMMxxxD
pins: 1 So-, 2 NC, 3 Sov+, 11 Si+, 12 Si-, 13 Po-, 14 Po+, 15 NC, 16 NC, 23 Pi+, 24 Pi-

## ZCMRxxxxD
designator U?
footprint ZCMRxxxxD
pins: 1 ZA1, 2 ZA2, 3 FB1, 4 FB2, 6 VD, 7 GND, 10 Vo+, 11 NC, 12 Vo-, 13 Io-, 14 NC, 15 Io+, 21 NC, 22 B, 23 B, 24 A

## ZLG1002
designator U?
ZLG1002-HCP90023,SOT-23-6,ZLG
footprint ZLG1002
pins: 1 SVCC, 2 PGND, 3 SGND, 4 SW1, 5 PVCC, 6 SW2

## ZY0FBxxD-2W
designator U?
footprint ZY0FBxxD-2W
pins: 1 AC(L), 2 AC(N), 3 -Vo, 4 +Vo, 5 PG

## ZY0FBxxP-3W
designator U?
footprint ZY0FBxxP-3W
pins: 1 AC(L), 2 AC(N), 3 -Vo, 4 +Vo

## ZY0GAxxCD-5W
designator U?
footprint ZY0GAxxCD-5W
pins: 1 AC(L), 2 AC(N), 3 FG, 4 -Vo, 6 COM, 8 +Vo

## ZY0GBxxD-5W
designator U?
footprint ZY0GBxxD-5W (120426 修改 by kong)
pins: 1 AC(L), 2 AC(N), 3 FG, 4 -Vo, 8 +Vo

## ZY0GBxxD-10W
designator U?
footprint ZY0GBxxD-10W (120426 修改 by kong)
pins: 1 AC(L), 2 AC(N), 3 FG, 5 -Vo, 9 +Vo

## ZY0GBxxD-15W
designator U?
footprint ZY0GBxxD-15W (120426 修改 by kong)
pins: 1 AC(L), 2 AC(N), 3 FG, 5 -Vo, 9 +Vo

## ZY0GBxxD-25W
designator U?
footprint ZY0GBxxD-25W (120426 修改 by kong)
pins: 1 AC(L), 2 AC(N), 3 FG, 5 -Vo, 9 +Vo

## ZY0GBxxP-2W
designator U?
footprint ZY0GBxxP-2W
pins: 1 AC(L), 2 AC(N), 3 -Vo, 4 +Vo

## ZY0GDxxxxDIx-15W
designator U?
footprint ZY0GDxxxxDIx-15W
pins: 1 AC(L), 2 AC(N), 3 FG, 5 -Vo1, 6 +Vo1, 8 -Vo2, 9 +Vo2

## ZY0IFBxxP-3W
designator U?
footprint ZY0IFBxxP-3W
pins: 1 AC(L), 2 AC(N), 3 -Vo, 4 +Vo

## ZY0IGBxxD-5W
designator U?
footprint ZY0IGBxxD-5W (120426 修改 by kong)
pins: 1 AC(L), 2 AC(N), 3 FG, 4 -Vo, 8 +Vo

## ZY0JGAxxCD-10W
designator U?
footprint ZY0JGAxxCD-10W
pins: 1 AC(L), 2 AC(N), 3 FG, 4 -Vo, 6 COM, 8 +Vo

## ZY0JGAxxD-5W
designator U?
footprint ZY0JGAxxD-5W
pins: 1 AC(L), 2 AC(N), 3 FG, 4 -Vo, 6 COM, 8 +Vo

## ZY0JGBxxCD-5W
designator U?
footprint ZY0JGBxxCD-5W
pins: 1 AC(L), 2 AC(N), 3 FG, 4 -Vo, 8 +Vo

## ZY0JGBxxCD-10W
designator U?
footprint ZY0JGBxxCD-10W
pins: 1 AC(L), 2 AC(N), 3 FG, 4 -Vo, 8 +Vo

## ZY0JGBxxD-15W
designator U?
footprint ZY0JGBxxD-15W
pins: 1 AC(L), 2 AC(N), 3 FG, 4 -Vo, 8 +Vo

## ZY0JGBxxOS-2W
designator U?
footprint ZY0JGBxxOS-2W
pins: 1 AC(L), 2 AC(N), 3 VC+, 4 VC-, 5 -Vo, 6 +Vo

## ZY0JGBxxP-10W
designator U?
footprint ZY0JGBxxP-10W
pins: 1 AC(L), 2 AC(N), 3 +Vo, 4 -Vo

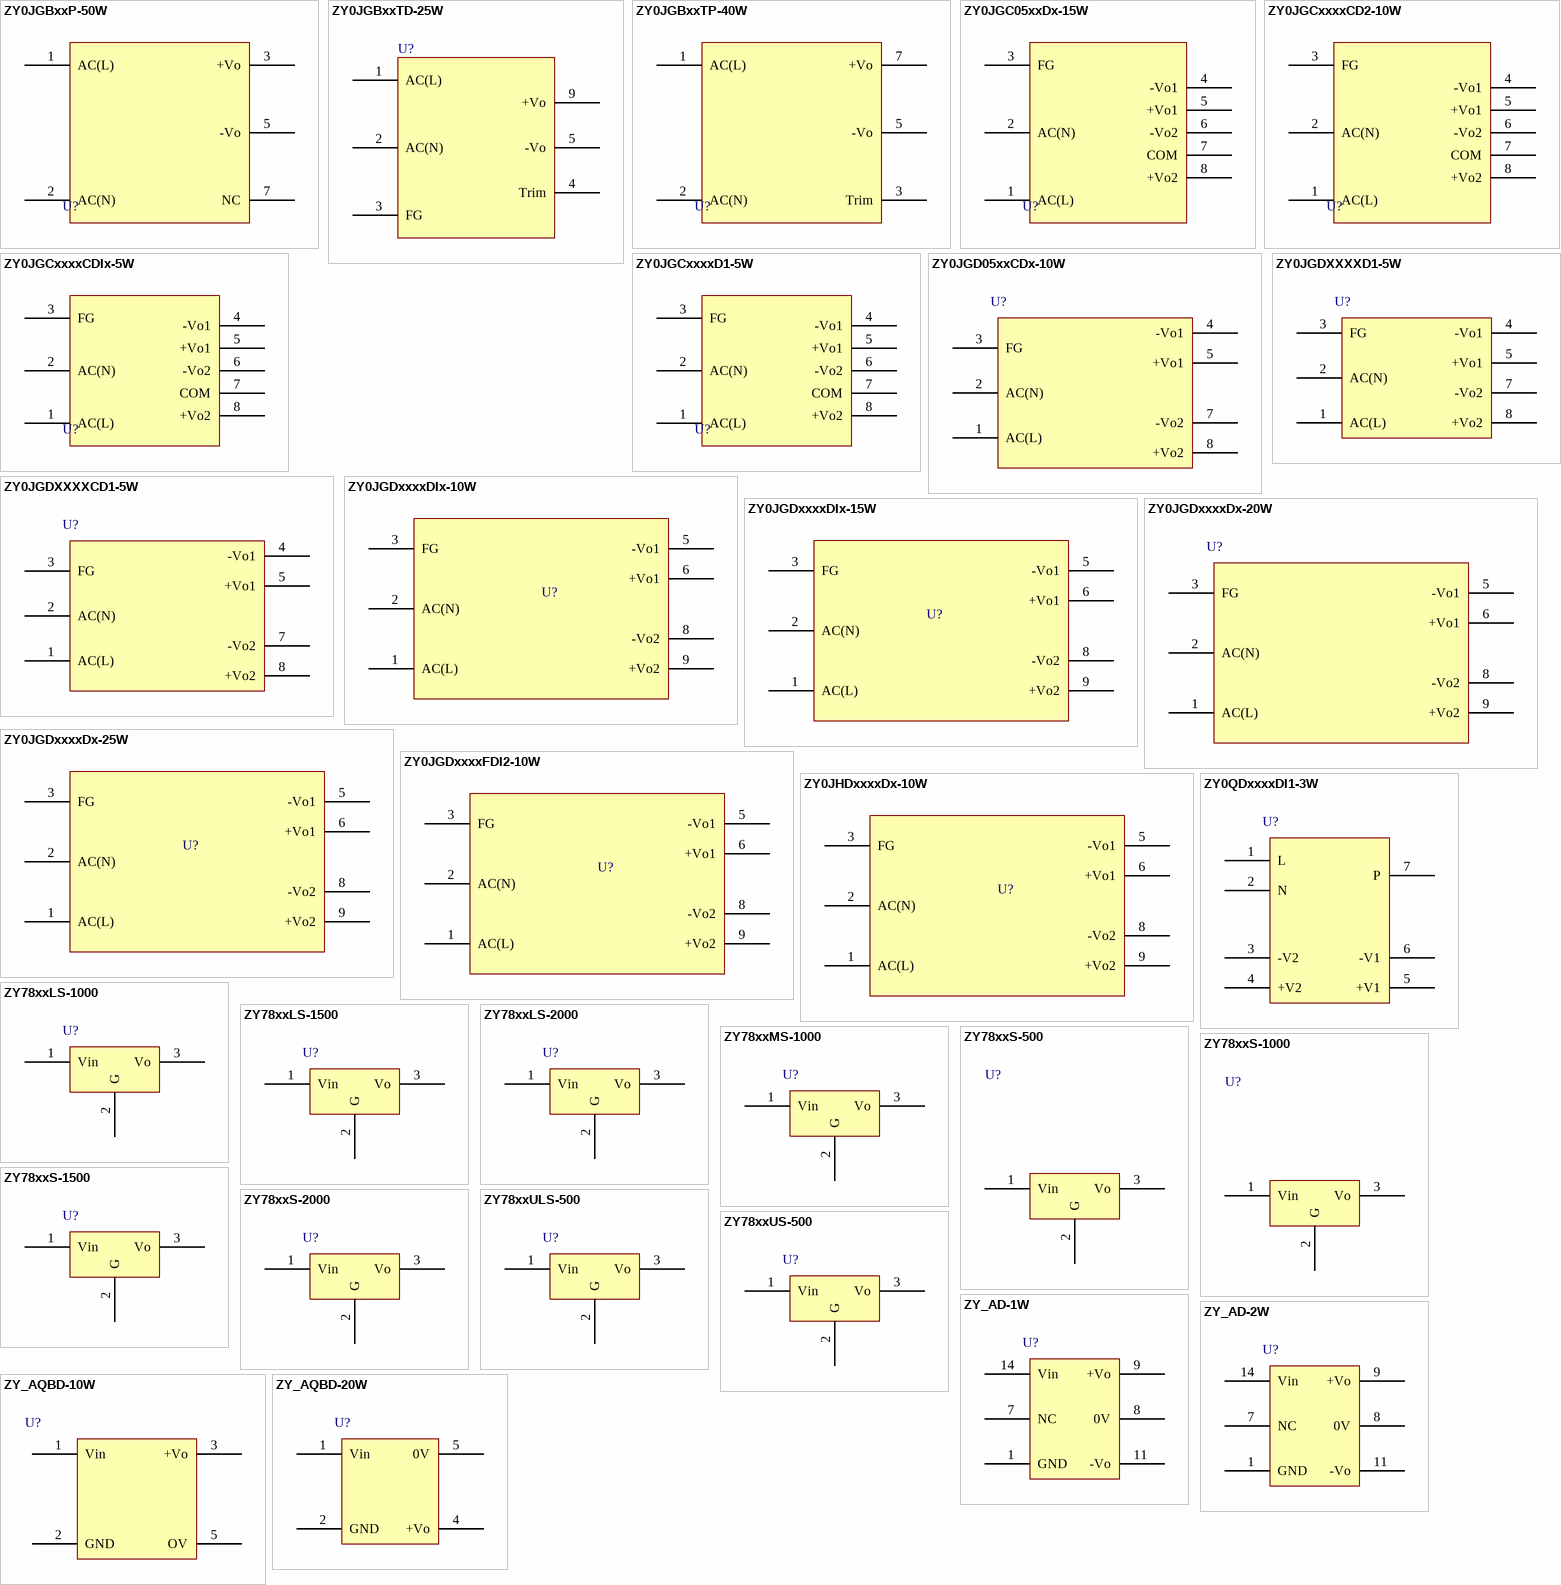
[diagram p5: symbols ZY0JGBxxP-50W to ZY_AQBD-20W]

## ZY0JGBxxP-50W
designator U?
footprint ZY0JGBxxP-50W
pins: 1 AC(L), 2 AC(N), 3 +Vo, 5 -Vo, 7 NC

## ZY0JGBxxTD-25W
designator U?
footprint ZY0JGBxxTD-25W
pins: 1 AC(L), 2 AC(N), 3 FG, 4 Trim, 5 -Vo, 9 +Vo

## ZY0JGBxxTP-40W
designator U?
footprint ZY0JGBxxTP-40W
pins: 1 AC(L), 2 AC(N), 3 Trim, 5 -Vo, 7 +Vo

## ZY0JGC05xxDx-15W
designator U?
footprint ZY0JGC05xxDx-15W
pins: 1 AC(L), 2 AC(N), 3 FG, 4 -Vo1, 5 +Vo1, 6 -Vo2, 7 COM, 8 +Vo2

## ZY0JGCxxxxCD2-10W
designator U?
footprint ZY0JGCxxxxCD2-10W
pins: 1 AC(L), 2 AC(N), 3 FG, 4 -Vo1, 5 +Vo1, 6 -Vo2, 7 COM, 8 +Vo2

## ZY0JGCxxxxCDIx-5W
designator U?
footprint ZY0JGCxxxxCDIx-5W
pins: 1 AC(L), 2 AC(N), 3 FG, 4 -Vo1, 5 +Vo1, 6 -Vo2, 7 COM, 8 +Vo2

## ZY0JGCxxxxD1-5W
designator U?
footprint ZY0JGCxxxxD1-5W
pins: 1 AC(L), 2 AC(N), 3 FG, 4 -Vo1, 5 +Vo1, 6 -Vo2, 7 COM, 8 +Vo2

## ZY0JGD05xxCDx-10W
designator U?
footprint ZY0JGD05xxCDx-10W
pins: 1 AC(L), 2 AC(N), 3 FG, 4 -Vo1, 5 +Vo1, 7 -Vo2, 8 +Vo2

## ZY0JGDXXXXCD1-5W
designator U?
footprint ZY0JGDxxxxCD1-5W
pins: 1 AC(L), 2 AC(N), 3 FG, 4 -Vo1, 5 +Vo1, 7 -Vo2, 8 +Vo2

## ZY0JGDXXXXD1-5W
designator U?
footprint ZY0JGDXXXXD1-5W
pins: 1 AC(L), 2 AC(N), 3 FG, 4 -Vo1, 5 +Vo1, 7 -Vo2, 8 +Vo2

## ZY0JGDxxxxDIx-10W
designator U?
footprint ZY0JGDxxxxDIx-10W
pins: 1 AC(L), 2 AC(N), 3 FG, 5 -Vo1, 6 +Vo1, 8 -Vo2, 9 +Vo2

## ZY0JGDxxxxDIx-15W
designator U?
footprint ZY0JGDxxxxDIx-15W
pins: 1 AC(L), 2 AC(N), 3 FG, 5 -Vo1, 6 +Vo1, 8 -Vo2, 9 +Vo2

## ZY0JGDxxxxDx-20W
designator U?
footprint ZY0JGDxxxxDx-20W
pins: 1 AC(L), 2 AC(N), 3 FG, 5 -Vo1, 6 +Vo1, 8 -Vo2, 9 +Vo2

## ZY0JGDxxxxDx-25W
designator U?
footprint ZY0JGDxxxxDx-25W
pins: 1 AC(L), 2 AC(N), 3 FG, 5 -Vo1, 6 +Vo1, 8 -Vo2, 9 +Vo2

## ZY0JGDxxxxFDI2-10W
designator U?
footprint ZY0JGDxxxxFDI2-10W
pins: 1 AC(L), 2 AC(N), 3 FG, 5 -Vo1, 6 +Vo1, 8 -Vo2, 9 +Vo2

## ZY0JHDxxxxDx-10W
designator U?
footprint ZY0JHDxxxxDx-10W
pins: 1 AC(L), 2 AC(N), 3 FG, 5 -Vo1, 6 +Vo1, 8 -Vo2, 9 +Vo2

## ZY0QDxxxxDI1-3W
designator U?
footprint ZY0QDxxxxDI1-3W
pins: 1 L, 2 N, 3 -V2, 4 +V2, 5 +V1, 6 -V1, 7 P

## ZY78xxLS-1000
designator U?
footprint ZY78xxLS-1000
pins: 1 Vin, 2 G, 3 Vo

## ZY78xxLS-1500
designator U?
footprint ZY78xxLS-1500
pins: 1 Vin, 2 G, 3 Vo

## ZY78xxLS-2000
designator U?
footprint ZY78xxLS-2000
pins: 1 Vin, 2 G, 3 Vo

## ZY78xxMS-1000
designator U?
footprint ZY78xxMS-1000
pins: 1 Vin, 2 G, 3 Vo

## ZY78xxS-500
designator U?
footprint ZY78xxS-500
pins: 1 Vin, 2 G, 3 Vo

## ZY78xxS-1000
designator U?
footprint ZY78xxS-1000
pins: 1 Vin, 2 G, 3 Vo

## ZY78xxS-1500
designator U?
footprint ZY78xxS-1500
pins: 1 Vin, 2 G, 3 Vo

## ZY78xxS-2000
designator U?
footprint ZY78xxS-2000
pins: 1 Vin, 2 G, 3 Vo

## ZY78xxULS-500
designator U?
footprint ZY78xxULS-500
pins: 1 Vin, 2 G, 3 Vo

## ZY78xxUS-500
designator U?
footprint ZY78xxUS-500
pins: 1 Vin, 2 G, 3 Vo

## ZY_AD-1W
designator U?
footprint ZY_AD-1W
pins: 1 GND, 7 NC, 8 0V, 9 +Vo, 11 -Vo, 14 Vin

## ZY_AD-2W
designator U?
footprint ZY_AD-2W
pins: 1 GND, 7 NC, 8 0V, 9 +Vo, 11 -Vo, 14 Vin

## ZY_AQBD-10W
designator U?
footprint ZY_AQBD-10W
pins: 1 Vin, 2 GND, 3 +Vo, 5 OV

## ZY_AQBD-20W
designator U?
footprint ZY_AQBD-20W
pins: 1 Vin, 2 GND, 4 +Vo, 5 0V

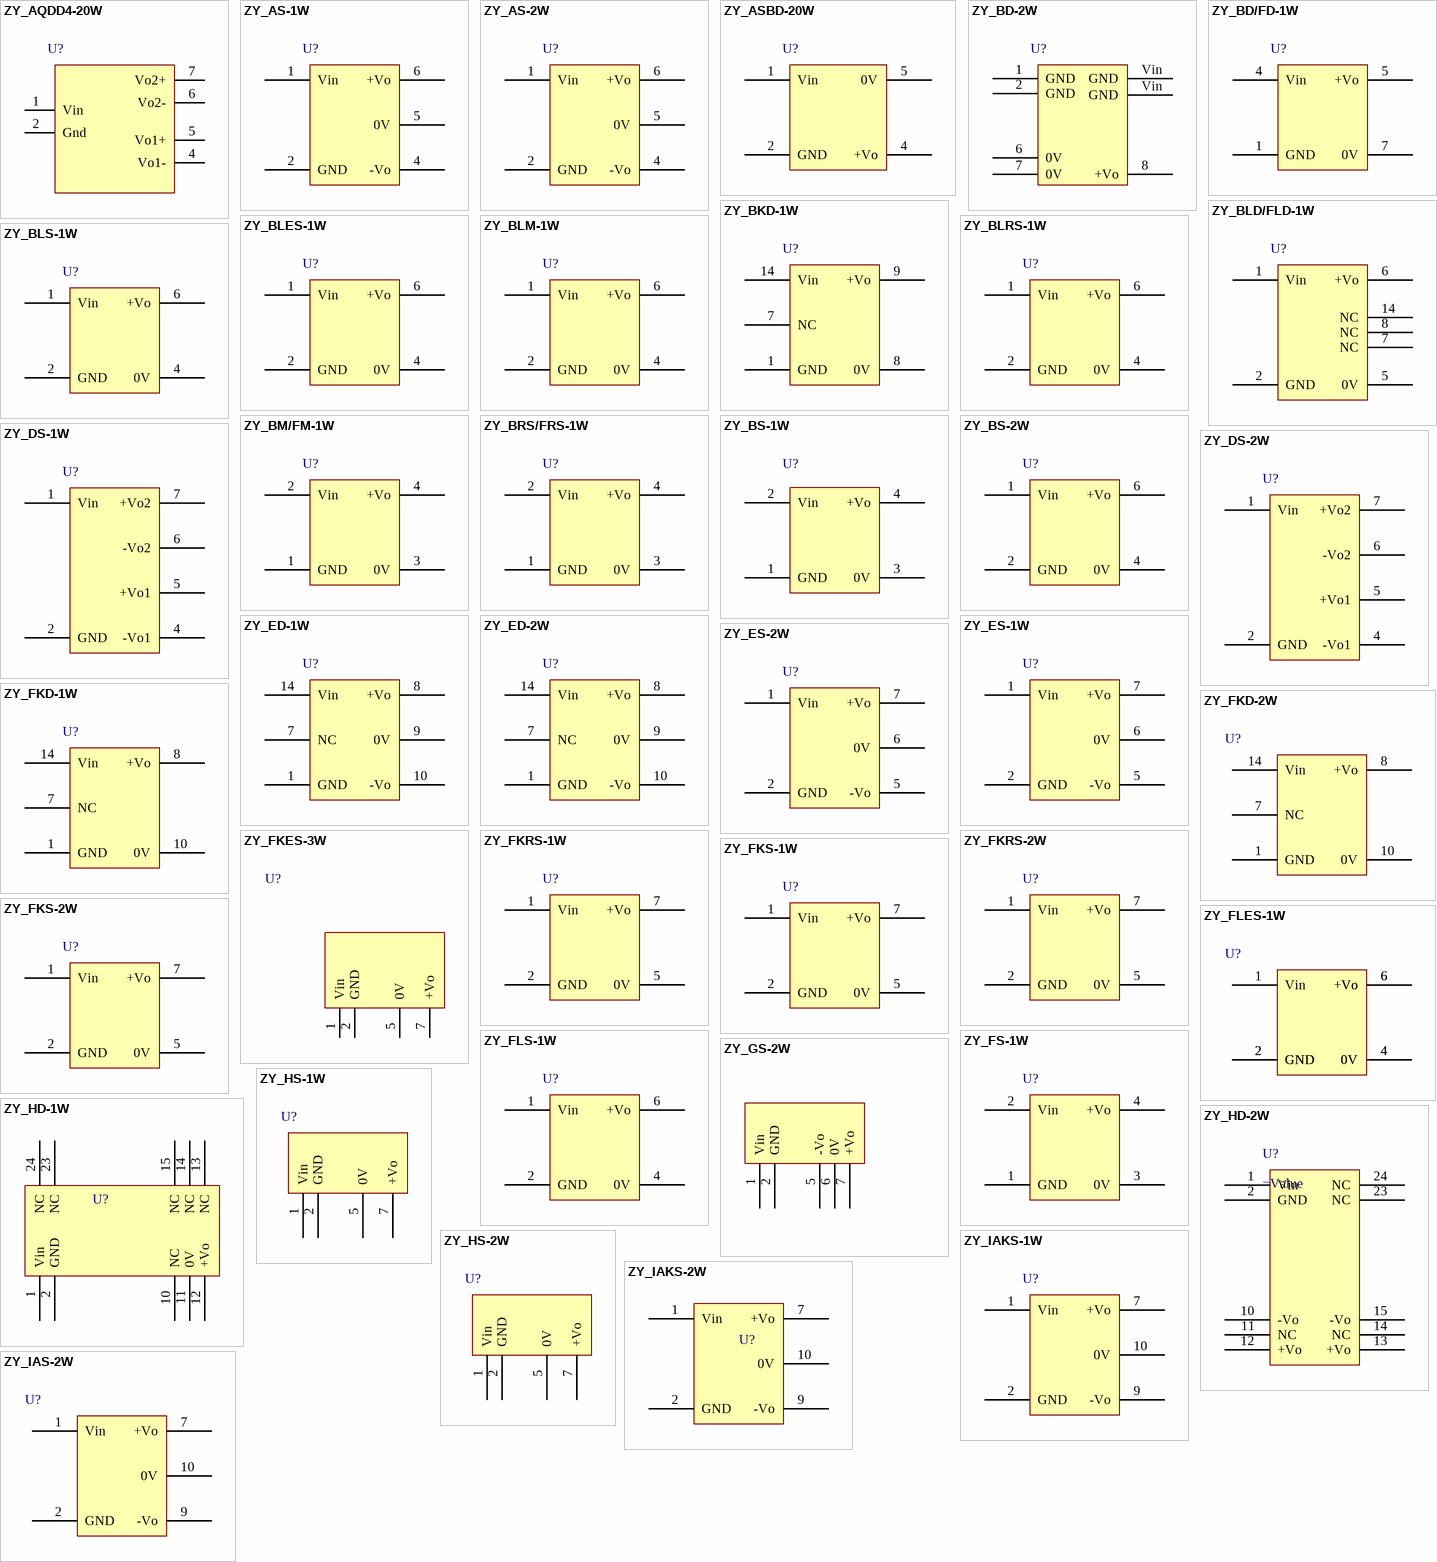
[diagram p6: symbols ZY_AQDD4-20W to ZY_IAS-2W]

## ZY_AQDD4-20W
designator U?
footprint ZY_AQDD4-20W
pins: 1 Vin, 2 Gnd, 4 Vo1-, 5 Vo1+, 6 Vo2-, 7 Vo2+

## ZY_AS-1W
designator U?
footprint ZY_AS-1W (定压输入隔离非稳压正、负双输出)
pins: 1 Vin, 2 GND, 4 -Vo, 5 0V, 6 +Vo

## ZY_AS-2W
designator U?
footprint ZY_AS-2W (定压输入隔离非稳压正、负双输出)
pins: 1 Vin, 2 GND, 4 -Vo, 5 0V, 6 +Vo

## ZY_ASBD-20W
designator U?
footprint ZY_ASBD-20W
pins: 1 Vin, 2 GND, 4 +Vo, 5 0V

## ZY_BD-2W
designator U?
footprint ZY_BD-2W
pins: 1 GND, 2 GND, 6 0V, 7 0V, 8 +Vo, Vin GND, Vin GND

## ZY_BD/FD-1W
designator U?
footprint ZY_BD/FD-1W (定压输入隔离非稳压单输出)
pins: 1 GND, 4 Vin, 5 +Vo, 7 0V

## ZY_BKD-1W
designator U?
footprint ZY_BKD-1W
pins: 1 GND, 7 NC, 8 0V, 9 +Vo, 14 Vin

## ZY_BLD/FLD-1W
designator U?
footprint ZY_BLD/FLD-1W (定压输入隔离非稳压单输出)
pins: 1 Vin, 2 GND, 5 0V, 6 +Vo, 7 NC, 8 NC, 14 NC

## ZY_BLES-1W
designator U?
footprint ZY_BLES-1W
pins: 1 Vin, 2 GND, 4 0V, 6 +Vo

## ZY_BLM-1W
designator U?
footprint ZY_BLM-1W
pins: 1 Vin, 2 GND, 4 0V, 6 +Vo

## ZY_BLRS-1W
designator U?
footprint ZY_BLRS-1W
pins: 1 Vin, 2 GND, 4 0V, 6 +Vo

## ZY_BLS-1W
designator U?
footprint ZY_BLS-1W (定压输入隔离非稳压单输出)
pins: 1 Vin, 2 GND, 4 0V, 6 +Vo

## ZY_BM/FM-1W
designator U?
footprint ZY_BM/FM-1W
pins: 1 GND, 2 Vin, 3 0V, 4 +Vo

## ZY_BRS/FRS-1W
designator U?
footprint ZY_BRS/FRS-1W
pins: 1 GND, 2 Vin, 3 0V, 4 +Vo

## ZY_BS-1W
designator U?
footprint ZY_BS-1W (定压输入隔离非稳压单输出)
pins: 1 GND, 2 Vin, 3 0V, 4 +Vo

## ZY_BS-2W
designator U?
footprint ZY_BS-2W (定压输入隔离非稳压单输出)
pins: 1 Vin, 2 GND, 4 0V, 6 +Vo

## ZY_DS-1W
designator U?
footprint ZY_DS-1W
pins: 1 Vin, 2 GND, 4 -Vo1, 5 +Vo1, 6 -Vo2, 7 +Vo2

## ZY_DS-2W
designator U?
footprint ZY_DS-2W (定压输入隔离非稳压双输出)
pins: 1 Vin, 2 GND, 4 -Vo1, 5 +Vo1, 6 -Vo2, 7 +Vo2

## ZY_ED-1W
designator U?
footprint ZY_ED-1W (定压输入隔离非稳压正、负输出)
pins: 1 GND, 7 NC, 8 +Vo, 9 0V, 10 -Vo, 14 Vin

## ZY_ED-2W
designator U?
footprint ZY_ED-2W
pins: 1 GND, 7 NC, 8 +Vo, 9 0V, 10 -Vo, 14 Vin

## ZY_ES-1W
designator U?
footprint ZY_ES-1W (定压输入隔离非稳压正、负输出)
pins: 1 Vin, 2 GND, 5 -Vo, 6 0V, 7 +Vo

## ZY_ES-2W
designator U?
footprint ZY_ES-2W (定压输入隔离非稳压双输出)
pins: 1 Vin, 2 GND, 5 -Vo, 6 0V, 7 +Vo

## ZY_FKD-1W
designator U?
footprint ZY_FKD-1W
pins: 1 GND, 7 NC, 8 +Vo, 10 0V, 14 Vin

## ZY_FKD-2W
designator U?
footprint ZY_FKD-2W
pins: 1 GND, 7 NC, 8 +Vo, 10 0V, 14 Vin

## ZY_FKES-3W
designator U?
footprint ZY_FKES-3W
pins: 1 Vin, 2 GND, 5 0V, 7 +Vo

## ZY_FKRS-1W
designator U?
footprint ZY_FKRS-1W
pins: 1 Vin, 2 GND, 5 0V, 7 +Vo

## ZY_FKRS-2W
designator U?
footprint ZY_FKRS-2W
pins: 1 Vin, 2 GND, 5 0V, 7 +Vo

## ZY_FKS-1W
designator U?
footprint ZY_FKS-1W
pins: 1 Vin, 2 GND, 5 0V, 7 +Vo

## ZY_FKS-2W
designator U?
footprint ZY_FKS-2W (定压输入隔离非稳压单输出)
pins: 1 Vin, 2 GND, 5 0V, 7 +Vo

## ZY_FLES-1W
designator U?
footprint ZY_FLES-1W
pins: 1 Vin, 2 GND, 2 GND, 4 0V, 4 0V, 6 +Vo, 6 +Vo

## ZY_FLS-1W
designator U?
footprint ZY_FLS-1W
pins: 1 Vin, 2 GND, 4 0V, 6 +Vo

## ZY_FS-1W
designator U?
footprint ZY_FS-1W (定压输入隔离非稳压单输出)
pins: 1 GND, 2 Vin, 3 0V, 4 +Vo

## ZY_GS-2W
designator U?
footprint ZY_GS-2W
pins: 1 Vin, 2 GND, 5 -Vo, 6 0V, 7 +Vo

## ZY_HD-1W
designator U?
footprint ZY_HD-1W
pins: 1 Vin, 2 GND, 10 NC, 11 0V, 12 +Vo, 13 NC, 14 NC, 15 NC, 23 NC, 24 NC

## ZY_HD-2W
designator U?
footprint ZY_HD-2W
pins: 1 Vin, 2 GND, 10 -Vo, 11 NC, 12 +Vo, 13 +Vo, 14 NC, 15 -Vo, 23 NC, 24 NC

## ZY_HS-1W
designator U?
footprint ZY_HS-1W
pins: 1 Vin, 2 GND, 5 0V, 7 +Vo

## ZY_HS-2W
designator U?
footprint ZY_HS-2W
pins: 1 Vin, 2 GND, 5 0V, 7 +Vo

## ZY_IAKS-1W
designator U?
footprint ZY_IAKS-1W (定压输入隔离稳压双输出)
pins: 1 Vin, 2 GND, 7 +Vo, 9 -Vo, 10 0V

## ZY_IAKS-2W
designator U?
footprint ZY_IAKS-2W
pins: 1 Vin, 2 GND, 7 +Vo, 9 -Vo, 10 0V

## ZY_IAS-2W
designator U?
footprint ZY_IAS-2W
pins: 1 Vin, 2 GND, 7 +Vo, 9 -Vo, 10 0V

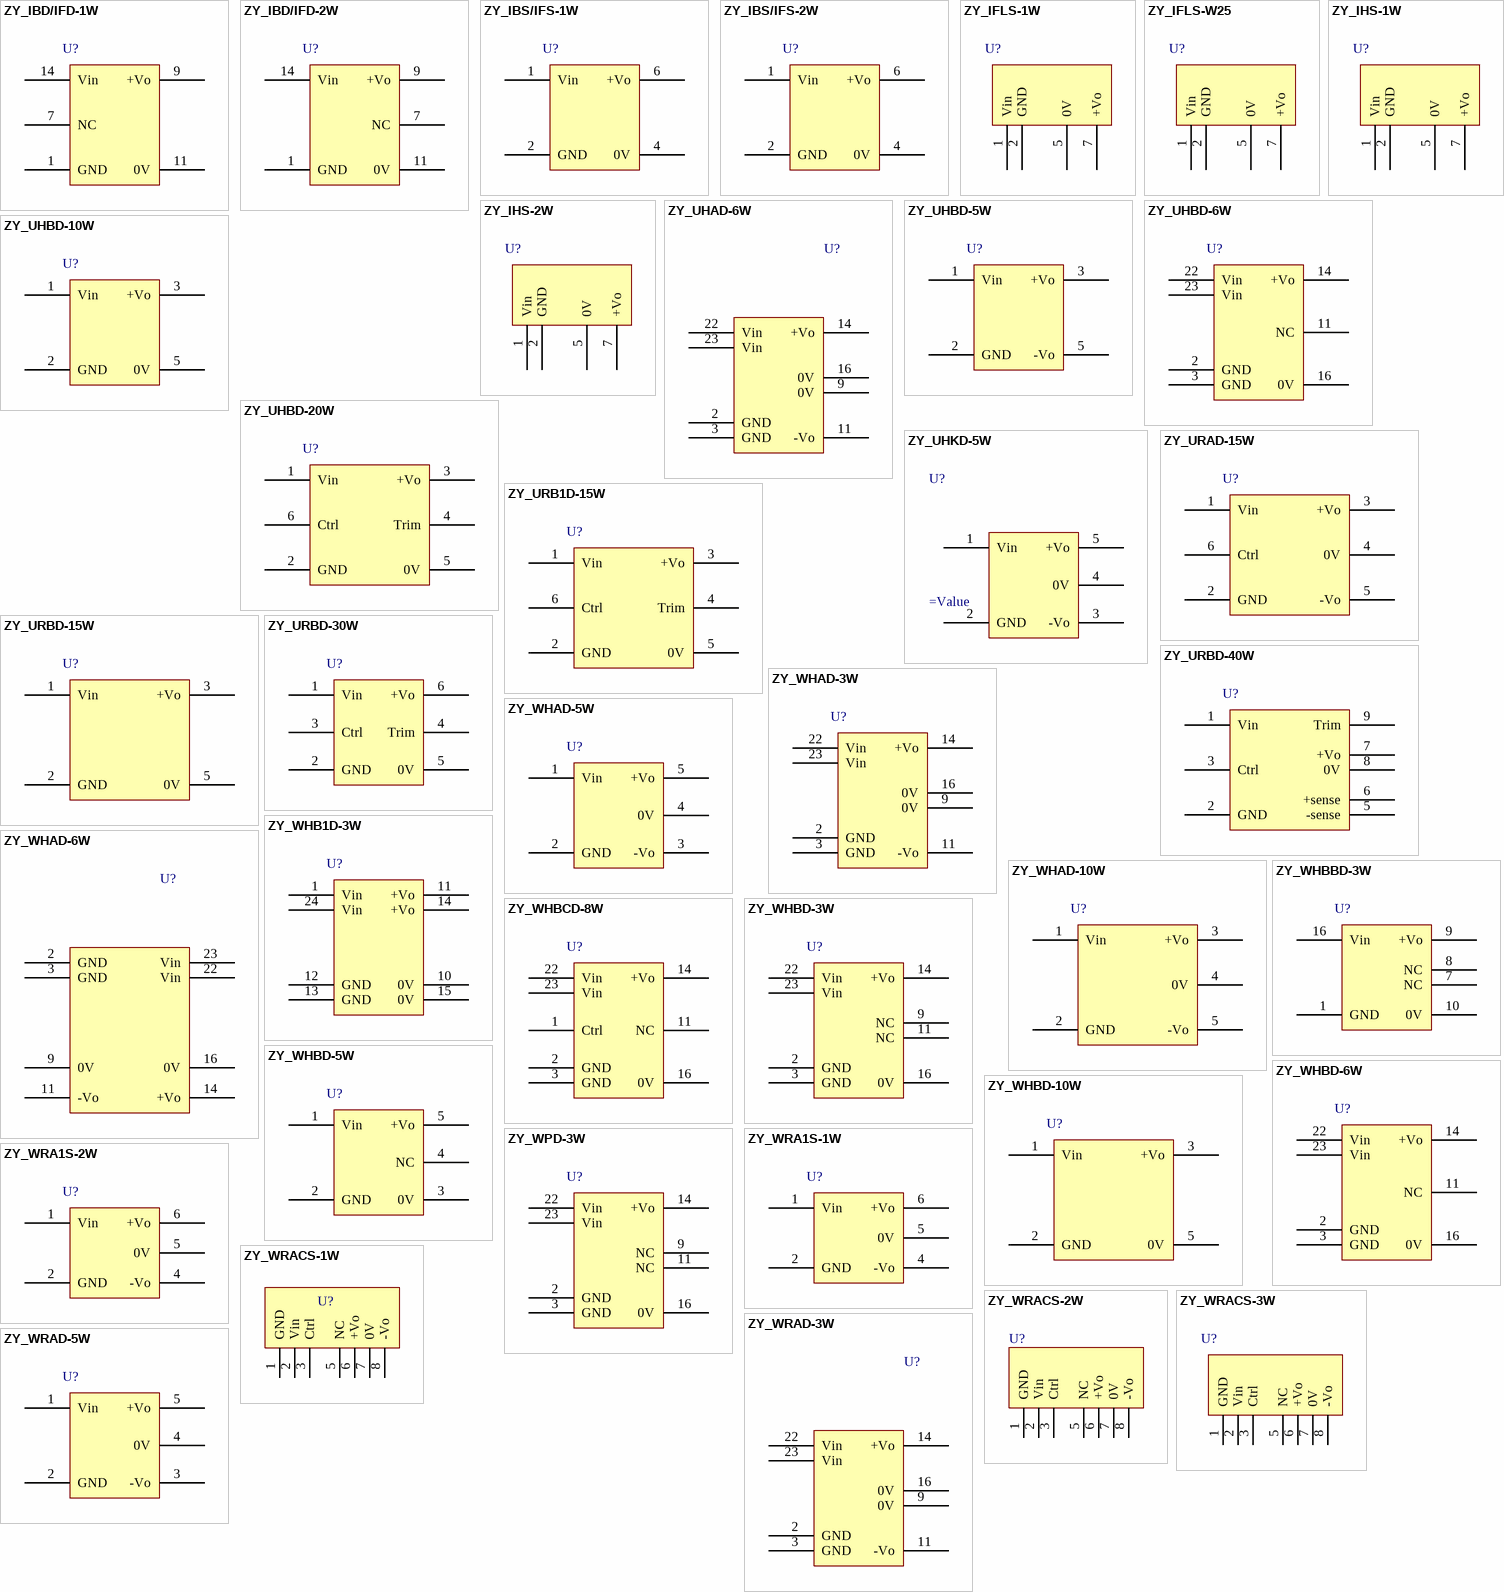
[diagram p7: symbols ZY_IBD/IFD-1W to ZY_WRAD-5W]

## ZY_IBD/IFD-1W
designator U?
footprint ZY_IBD/IFD-1W
pins: 1 GND, 7 NC, 9 +Vo, 11 0V, 14 Vin

## ZY_IBD/IFD-2W
designator U?
footprint ZY_IBD/IFD-2W
pins: 1 GND, 7 NC, 9 +Vo, 11 0V, 14 Vin

## ZY_IBS/IFS-1W
designator U?
footprint ZY_IBS/IFS-1W (定压输入隔离稳压单输出)
pins: 1 Vin, 2 GND, 4 0V, 6 +Vo

## ZY_IBS/IFS-2W
designator U?
footprint ZY_IBS/IFS-2W
pins: 1 Vin, 2 GND, 4 0V, 6 +Vo

## ZY_IFLS-1W
designator U?
footprint ZY_IFLS-1W
pins: 1 Vin, 2 GND, 5 0V, 7 +Vo

## ZY_IFLS-W25
designator U?
footprint ZY_IFLS-W25
pins: 1 Vin, 2 GND, 5 0V, 7 +Vo

## ZY_IHS-1W
designator U?
footprint ZY_IHS-1W
pins: 1 Vin, 2 GND, 5 0V, 7 +Vo

## ZY_IHS-2W
designator U?
footprint ZY_IHS-2W
pins: 1 Vin, 2 GND, 5 0V, 7 +Vo

## ZY_UHAD-6W
designator U?
footprint ZY_UHAD-6W
pins: 2 GND, 3 GND, 9 0V, 11 -Vo, 14 +Vo, 16 0V, 22 Vin, 23 Vin

## ZY_UHBD-5W
designator U?
footprint ZY_UHBD-5W
pins: 1 Vin, 2 GND, 3 +Vo, 5 -Vo

## ZY_UHBD-6W
designator U?
footprint ZY_UHBD-6W
pins: 2 GND, 3 GND, 11 NC, 14 +Vo, 16 0V, 22 Vin, 23 Vin

## ZY_UHBD-10W
designator U?
footprint ZY_UHBD-10W
pins: 1 Vin, 2 GND, 3 +Vo, 5 0V

## ZY_UHBD-20W
designator U?
footprint ZY_UHBD-20W
pins: 1 Vin, 2 GND, 3 +Vo, 4 Trim, 5 0V, 6 Ctrl

## ZY_UHKD-5W
designator U?
footprint ZY_UHKD-5W
pins: 1 Vin, 2 GND, 3 -Vo, 4 0V, 5 +Vo

## ZY_URAD-15W
designator U?
footprint ZY_URAD-15W
pins: 1 Vin, 2 GND, 3 +Vo, 4 0V, 5 -Vo, 6 Ctrl

## ZY_URB1D-15W
designator U?
footprint ZY_URB1D-15W
pins: 1 Vin, 2 GND, 3 +Vo, 4 Trim, 5 0V, 6 Ctrl

## ZY_URBD-15W
designator U?
footprint ZY_URBD-15W
pins: 1 Vin, 2 GND, 3 +Vo, 5 0V

## ZY_URBD-30W
designator U?
footprint ZY_URBD-30W
pins: 1 Vin, 2 GND, 3 Ctrl, 4 Trim, 5 0V, 6 +Vo

## ZY_URBD-40W
designator U?
footprint ZY_URBD-40W
pins: 1 Vin, 2 GND, 3 Ctrl, 5 -sense, 6 +sense, 7 +Vo, 8 0V, 9 Trim

## ZY_WHAD-3W
designator U?
footprint ZY_WHAD-3W (宽压输入隔离稳压双输出电源模块)
pins: 2 GND, 3 GND, 9 0V, 11 -Vo, 14 +Vo, 16 0V, 22 Vin, 23 Vin

## ZY_WHAD-5W
designator U?
footprint ZY_WHAD-5W
pins: 1 Vin, 2 GND, 3 -Vo, 4 0V, 5 +Vo

## ZY_WHAD-6W
designator U?
footprint ZY_WHAD-6W
pins: 2 GND, 3 GND, 9 0V, 11 -Vo, 14 +Vo, 16 0V, 22 Vin, 23 Vin

## ZY_WHAD-10W
designator U?
footprint ZY_WHAD-10W
pins: 1 Vin, 2 GND, 3 +Vo, 4 0V, 5 -Vo

## ZY_WHB1D-3W
designator U?
footprint ZY_WHB1D-3W
pins: 1 Vin, 10 0V, 11 +Vo, 12 GND, 13 GND, 14 +Vo, 15 0V, 24 Vin

## ZY_WHBBD-3W
designator U?
footprint ZY_WHBBD-3W
pins: 1 GND, 7 NC, 8 NC, 9 +Vo, 10 0V, 16 Vin

## ZY_WHBCD-8W
designator U?
footprint ZY_WHBCD-8W
pins: 1 Ctrl, 2 GND, 3 GND, 11 NC, 14 +Vo, 16 0V, 22 Vin, 23 Vin

## ZY_WHBD-3W
designator U?
footprint ZY_WHBD-3W (宽压输入隔离稳压单输出电源模块)
pins: 2 GND, 3 GND, 9 NC, 11 NC, 14 +Vo, 16 0V, 22 Vin, 23 Vin

## ZY_WHBD-5W
designator U?
footprint ZY_WHBD-5W
pins: 1 Vin, 2 GND, 3 0V, 4 NC, 5 +Vo

## ZY_WHBD-6W
designator U?
footprint ZY_WHBD-6W
pins: 2 GND, 3 GND, 11 NC, 14 +Vo, 16 0V, 22 Vin, 23 Vin

## ZY_WHBD-10W
designator U?
footprint ZY_WHBD-10W
pins: 1 Vin, 2 GND, 3 +Vo, 5 0V

## ZY_WPD-3W
designator U?
footprint ZY_WPD-3W (宽压输入非隔离稳压单输出)
pins: 2 GND, 3 GND, 9 NC, 11 NC, 14 +Vo, 16 0V, 22 Vin, 23 Vin

## ZY_WRA1S-1W
designator U?
footprint ZY_WRA1S-1W
pins: 1 Vin, 2 GND, 4 -Vo, 5 0V, 6 +Vo

## ZY_WRA1S-2W
designator U?
footprint ZY_WRA1S-2W
pins: 1 Vin, 2 GND, 4 -Vo, 5 0V, 6 +Vo

## ZY_WRACS-1W
designator U?
footprint ZY_WRACS-1W
pins: 1 GND, 2 Vin, 3 Ctrl, 5 NC, 6 +Vo, 7 0V, 8 -Vo

## ZY_WRACS-2W
designator U?
footprint ZY_WRACS-2W
pins: 1 GND, 2 Vin, 3 Ctrl, 5 NC, 6 +Vo, 7 0V, 8 -Vo

## ZY_WRACS-3W
designator U?
footprint ZY_WRACS-3W
pins: 1 GND, 2 Vin, 3 Ctrl, 5 NC, 6 +Vo, 7 0V, 8 -Vo

## ZY_WRAD-3W
designator U?
footprint ZY_WRAD-3W
pins: 2 GND, 3 GND, 9 0V, 11 -Vo, 14 +Vo, 16 0V, 22 Vin, 23 Vin

## ZY_WRAD-5W
designator U?
footprint ZY_WRAD-5W
pins: 1 Vin, 2 GND, 3 -Vo, 4 0V, 5 +Vo

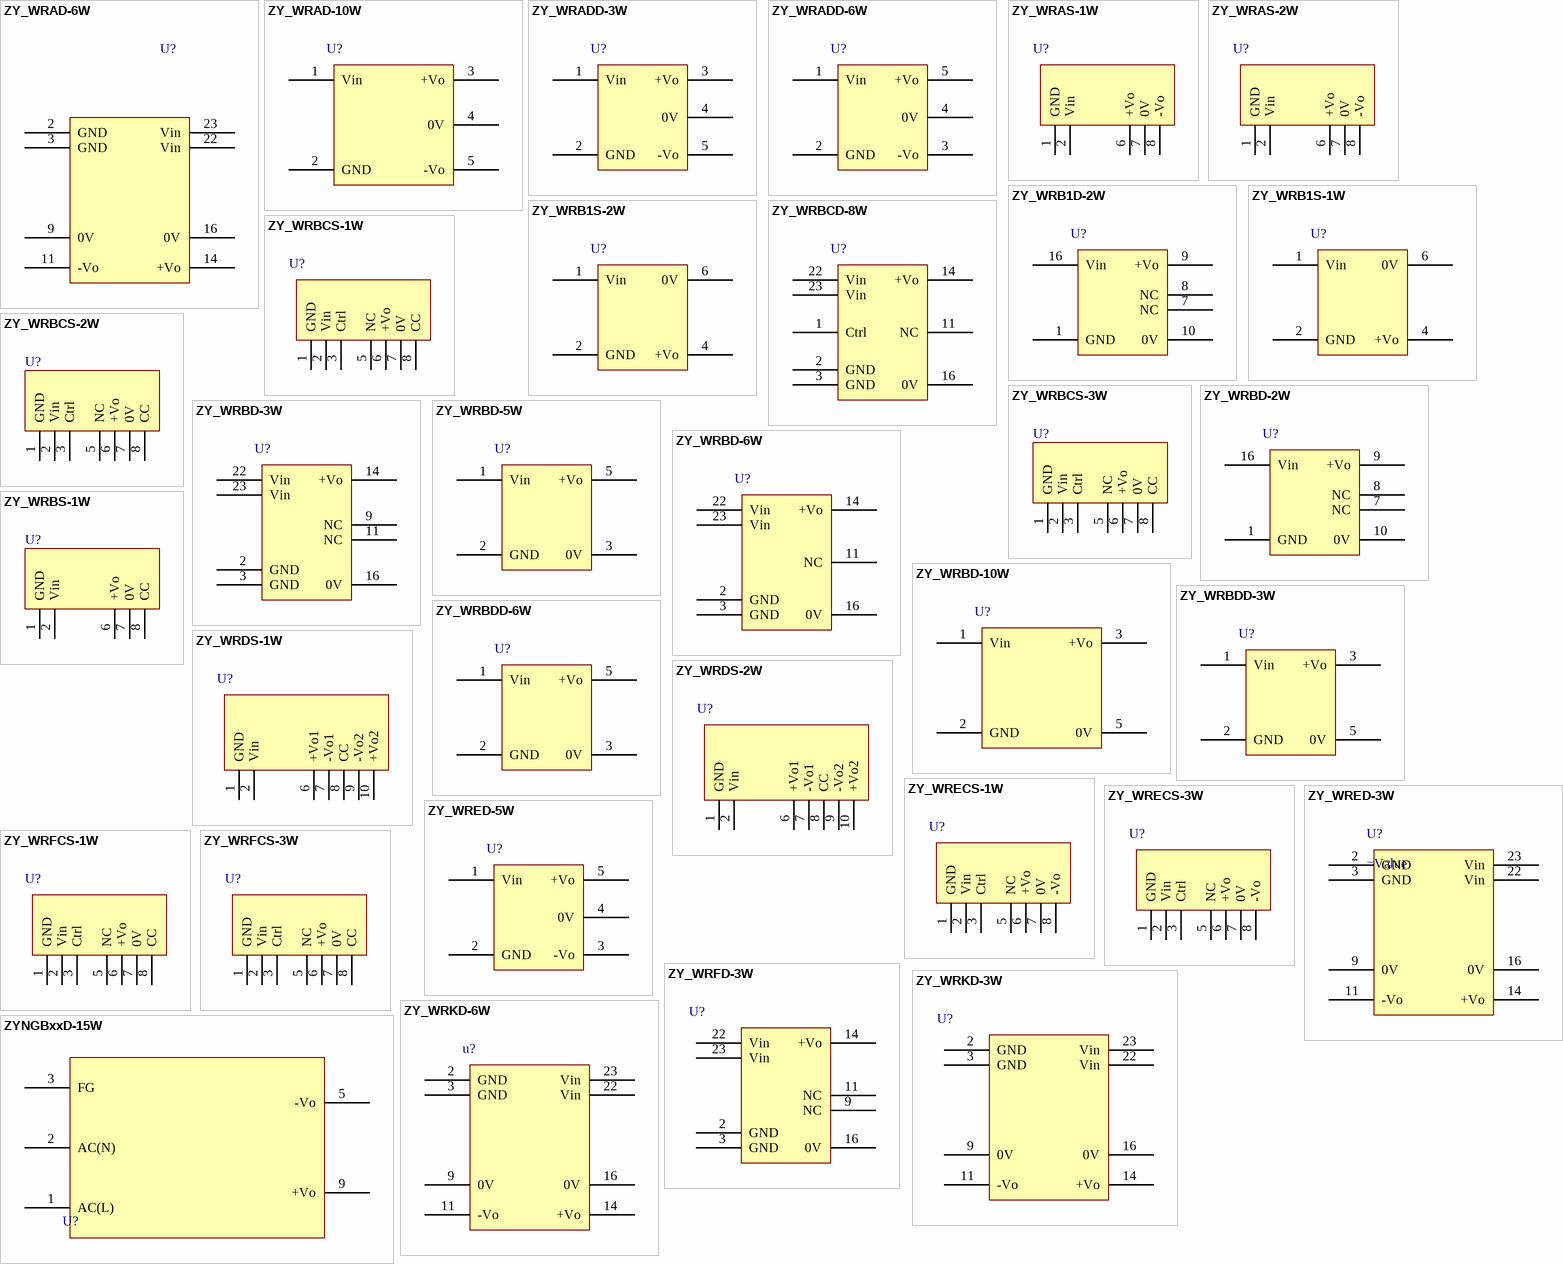
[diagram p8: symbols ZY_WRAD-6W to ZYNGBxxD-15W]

## ZY_WRAD-6W
designator U?
footprint ZY_WRAD-6W
pins: 2 GND, 3 GND, 9 0V, 11 -Vo, 14 +Vo, 16 0V, 22 Vin, 23 Vin

## ZY_WRAD-10W
designator U?
footprint ZY_WRAD-10W
pins: 1 Vin, 2 GND, 3 +Vo, 4 0V, 5 -Vo

## ZY_WRADD-3W
designator U?
footprint ZY_WRADD-3W
pins: 1 Vin, 2 GND, 3 +Vo, 4 0V, 5 -Vo

## ZY_WRADD-6W
designator U?
footprint ZY_WRADD-6W
pins: 1 Vin, 2 GND, 3 -Vo, 4 0V, 5 +Vo

## ZY_WRAS-1W
designator U?
footprint ZY_WRAS-1W
pins: 1 GND, 2 Vin, 6 +Vo, 7 0V, 8 -Vo

## ZY_WRAS-2W
designator U?
footprint ZY_WRAS-2W
pins: 1 GND, 2 Vin, 6 +Vo, 7 0V, 8 -Vo

## ZY_WRB1D-2W
designator U?
footprint ZY_WRB1D-2W
pins: 1 GND, 7 NC, 8 NC, 9 +Vo, 10 0V, 16 Vin

## ZY_WRB1S-1W
designator U?
footprint ZY_WRB1S-1W
pins: 1 Vin, 2 GND, 4 +Vo, 6 0V

## ZY_WRB1S-2W
designator U?
footprint ZY_WRB1S-2W
pins: 1 Vin, 2 GND, 4 +Vo, 6 0V

## ZY_WRBCD-8W
designator U?
footprint ZY_WRBCD-8W
pins: 1 Ctrl, 2 GND, 3 GND, 11 NC, 14 +Vo, 16 0V, 22 Vin, 23 Vin

## ZY_WRBCS-1W
designator U?
footprint ZY_WRBCS-1W
pins: 1 GND, 2 Vin, 3 Ctrl, 5 NC, 6 +Vo, 7 0V, 8 CC

## ZY_WRBCS-2W
designator U?
footprint ZY_WRBCS-2W
pins: 1 GND, 2 Vin, 3 Ctrl, 5 NC, 6 +Vo, 7 0V, 8 CC

## ZY_WRBCS-3W
designator U?
footprint ZY_WRBCS-3W
pins: 1 GND, 2 Vin, 3 Ctrl, 5 NC, 6 +Vo, 7 0V, 8 CC

## ZY_WRBD-2W
designator U?
footprint ZY_WRBD-2W
pins: 1 GND, 7 NC, 8 NC, 9 +Vo, 10 0V, 16 Vin

## ZY_WRBD-3W
designator U?
footprint ZY_WRBD-3W (宽压输入隔离稳压单输出电源模块)
pins: 2 GND, 3 GND, 9 NC, 11 NC, 14 +Vo, 16 0V, 22 Vin, 23 Vin

## ZY_WRBD-5W
designator U?
footprint ZY_WRBD-5W
pins: 1 Vin, 2 GND, 3 0V, 5 +Vo

## ZY_WRBD-6W
designator U?
footprint ZY_WRBD-6W
pins: 2 GND, 3 GND, 11 NC, 14 +Vo, 16 0V, 22 Vin, 23 Vin

## ZY_WRBD-10W
designator U?
footprint ZY_WRBD-10W
pins: 1 Vin, 2 GND, 3 +Vo, 5 0V

## ZY_WRBDD-3W
designator U?
footprint ZY_WRBDD-3W
pins: 1 Vin, 2 GND, 3 +Vo, 5 0V

## ZY_WRBDD-6W
designator U?
footprint ZY_WRBDD-6W
pins: 1 Vin, 2 GND, 3 0V, 5 +Vo

## ZY_WRBS-1W
designator U?
footprint ZY_WRBS-1W
pins: 1 GND, 2 Vin, 6 +Vo, 7 0V, 8 CC

## ZY_WRDS-1W
designator U?
footprint ZY_WRDS-1W
pins: 1 GND, 2 Vin, 6 +Vo1, 7 -Vo1, 8 CC, 9 -Vo2, 10 +Vo2

## ZY_WRDS-2W
designator U?
footprint ZY_WRDS-2W
pins: 1 GND, 2 Vin, 6 +Vo1, 7 -Vo1, 8 CC, 9 -Vo2, 10 +Vo2

## ZY_WRECS-1W
designator U?
footprint ZY_WRECS-1W
pins: 1 GND, 2 Vin, 3 Ctrl, 5 NC, 6 +Vo, 7 0V, 8 -Vo

## ZY_WRECS-3W
designator U?
footprint ZY_WRECS-3W
pins: 1 GND, 2 Vin, 3 Ctrl, 5 NC, 6 +Vo, 7 0V, 8 -Vo

## ZY_WRED-3W
designator U?
footprint ZY_WRED-3W
pins: 2 GND, 3 GND, 9 0V, 11 -Vo, 14 +Vo, 16 0V, 22 Vin, 23 Vin

## ZY_WRED-5W
designator U?
footprint ZY_WRED-5W
pins: 1 Vin, 2 GND, 3 -Vo, 4 0V, 5 +Vo

## ZY_WRFCS-1W
designator U?
footprint ZY_WRFCS-1W
pins: 1 GND, 2 Vin, 3 Ctrl, 5 NC, 6 +Vo, 7 0V, 8 CC

## ZY_WRFCS-3W
designator U?
footprint ZY_WRFCS-3W
pins: 1 GND, 2 Vin, 3 Ctrl, 5 NC, 6 +Vo, 7 0V, 8 CC

## ZY_WRFD-3W
designator U?
footprint ZY_WRFD-3W
pins: 2 GND, 3 GND, 9 NC, 11 NC, 14 +Vo, 16 0V, 22 Vin, 23 Vin

## ZY_WRKD-3W
designator U?
footprint ZY_WRKD-3W
pins: 2 GND, 3 GND, 9 0V, 11 -Vo, 14 +Vo, 16 0V, 22 Vin, 23 Vin

## ZY_WRKD-6W
designator u?
footprint ZY_WRKD-6W
pins: 2 GND, 3 GND, 9 0V, 11 -Vo, 14 +Vo, 16 0V, 22 Vin, 23 Vin

## ZYNGBxxD-15W
designator U?
footprint ZYNGBxxD-15W (120426 修改 by kong)
pins: 1 AC(L), 2 AC(N), 3 FG, 5 -Vo, 9 +Vo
